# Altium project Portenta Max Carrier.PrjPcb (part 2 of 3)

## Sheet HDConn_FEMALE.SchDoc: HD Connectors female
size A3; Author: Arturo Guadalupi; CompanyName: Arduino srl; DocumentNumber: ABX00043; Revision: V3.10; SheetNumber: 2; SheetTotal: 14; RevAuthor: S. Navaretti
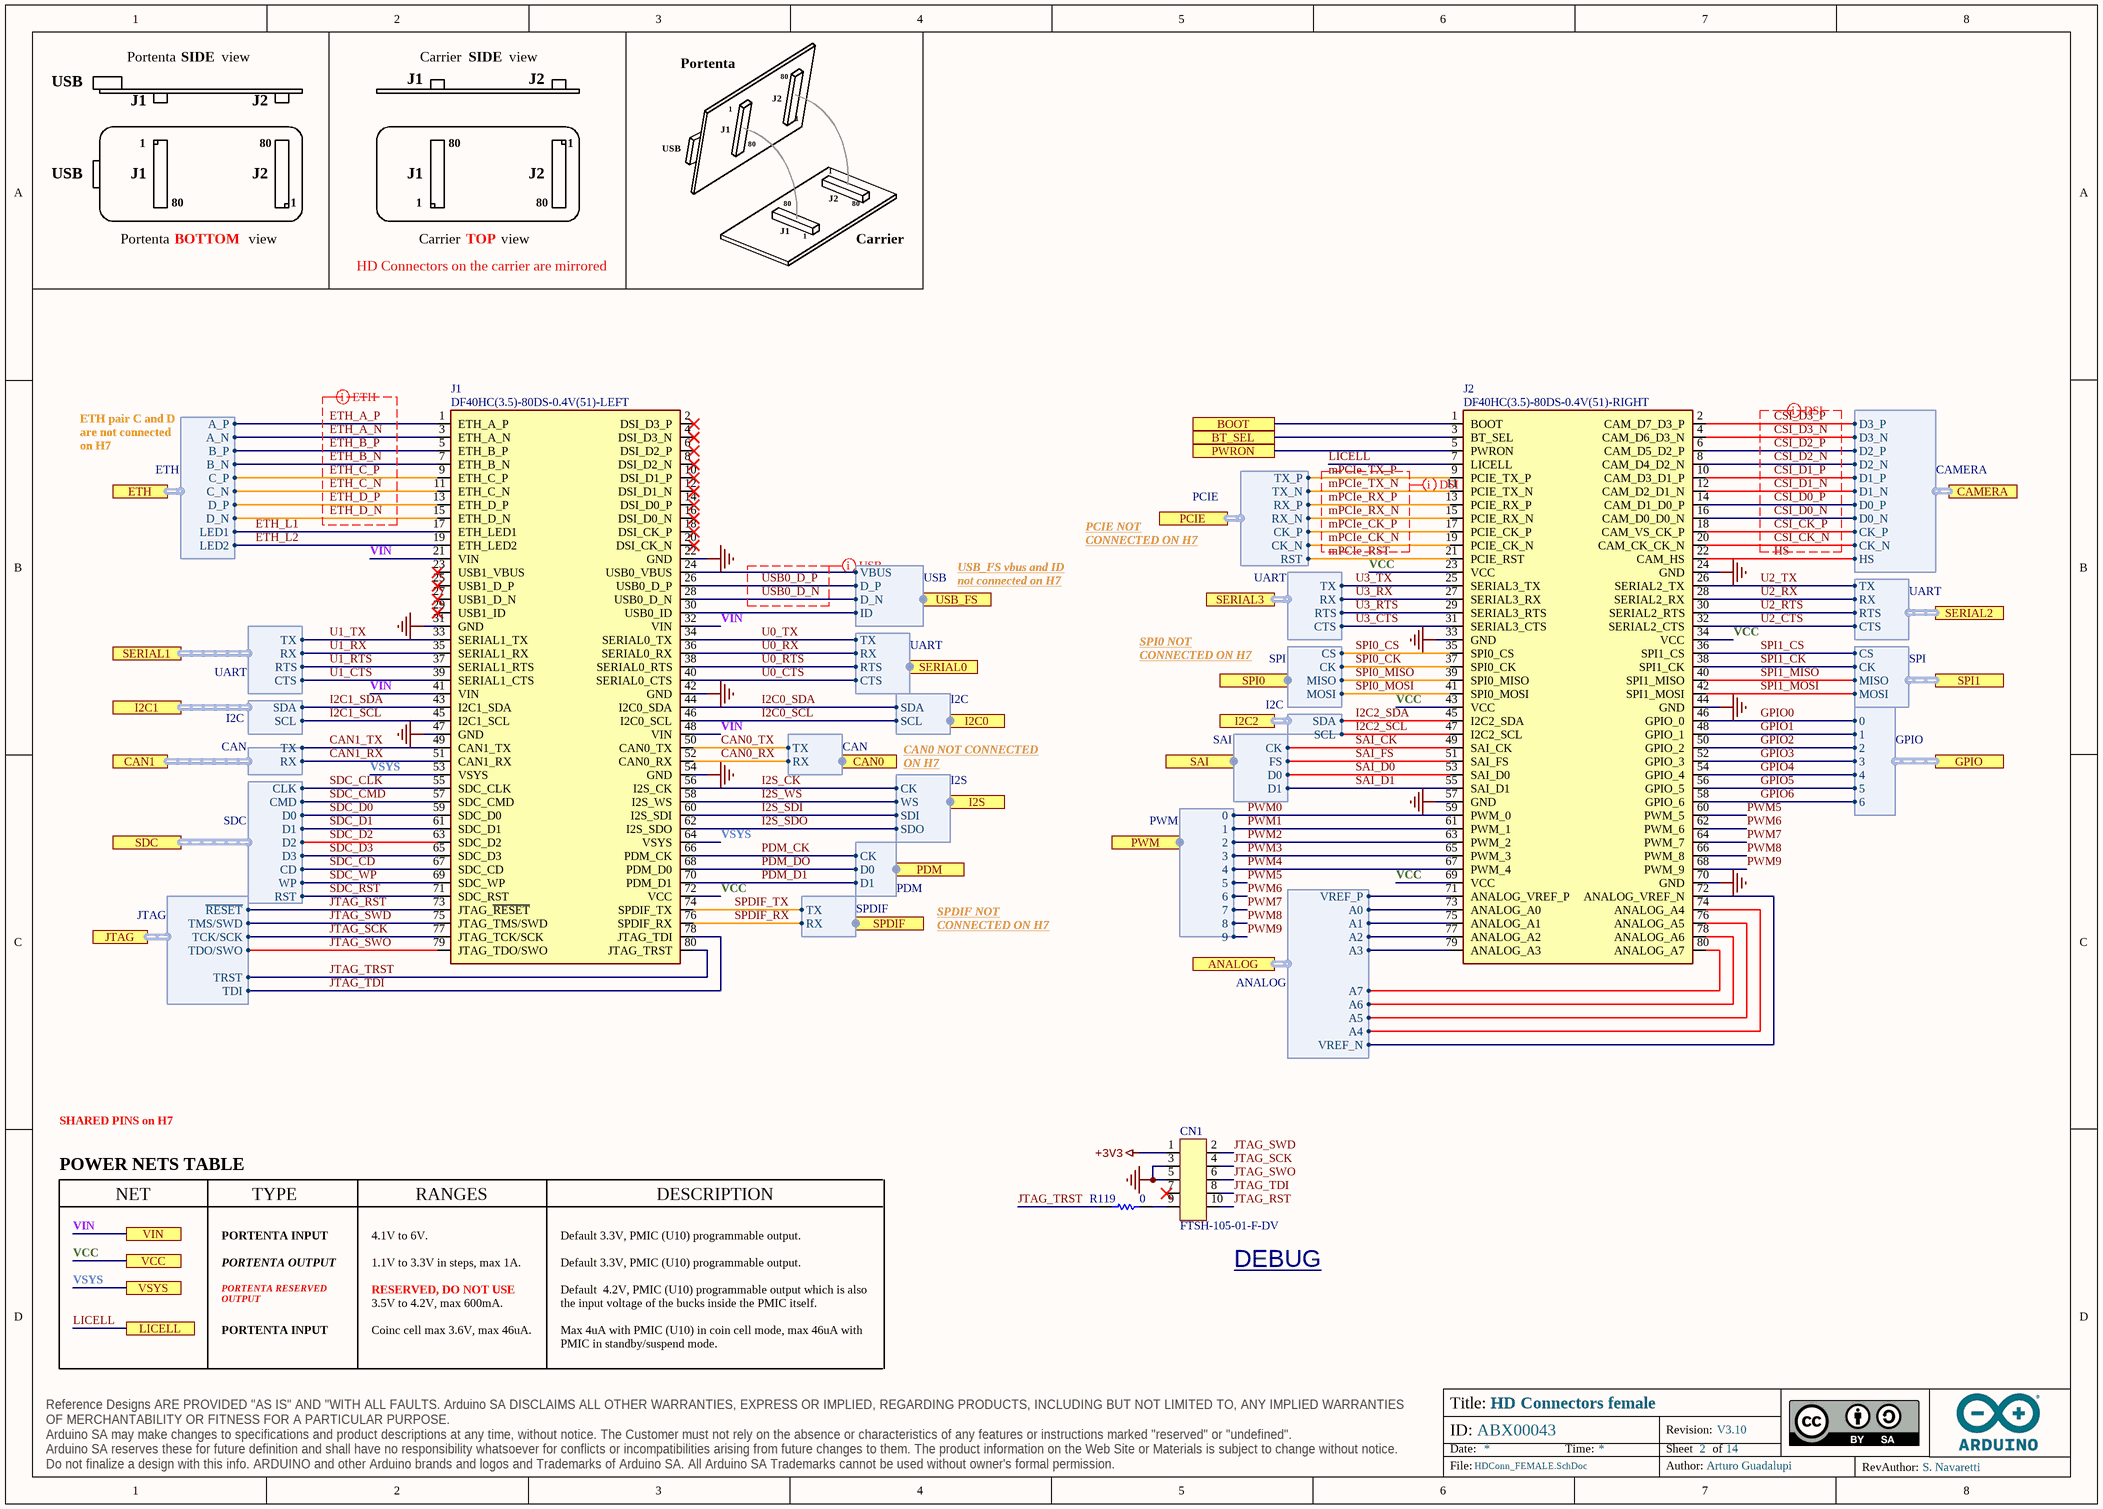
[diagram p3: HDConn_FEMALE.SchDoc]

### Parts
CN1  FTSH-105-01-F-DV  [FTSH-105-01-F-DV-Footprint-1]
J1  DF40HC(3.5)-80DS-0.4V(51)-LEFT  [DF40HC(3.5)-80DS-0.4V(51)-Footprint-1]
J2  DF40HC(3.5)-80DS-0.4V(51)-RIGHT  [DF40HC(3.5)-80DS-0.4V(51)-Footprint-1]
R119  value 0  [RES-0402]  (hidden comment: CRCW04020000Z0EDC)

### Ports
ANALOG (harness ANALOG), BOOT, BT_SEL, CAMERA (harness CAMERA), CAN0 (harness CAN), CAN1 (harness CAN), ETH (harness ETH), GPIO (harness GPIO), I2C0 (harness I2C), I2C1 (harness I2C), I2C2 (harness I2C), I2S (harness I2S), JTAG (harness JTAG), LICELL, PCIE (harness PCIE), PDM (harness PDM), PWM (harness PWM), PWRON, SAI (harness SAI), SDC (harness SDC), SERIAL0 (harness UART), SERIAL1 (harness UART), SERIAL2 (harness UART), SERIAL3 (harness UART), SPDIF (harness SPDIF), SPI0 (harness SPI), SPI1 (harness SPI), USB_FS (harness USB), VCC, VIN, VSYS

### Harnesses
ANALOG: VREF_P, A0, A1, A2, A3, A7, A6, A5, A4, VREF_N
PWM: 0, 1, 2, 3, 4, 5, 6, 7, 8, 9
GPIO: 0, 1, 2, 3, 4, 5, 6
ETH: A_P, A_N, B_P, B_N, C_P, C_N, D_P, D_N, LED1, LED2
UART: RX, TX, RTS, CTS
I2C: SCL, SDA
CAN: RX, TX
SDC: CLK, CMD, D0, D1, D2, D3, CD, WP, RST
JTAG: ~{RESET}, TCK/SCK, TDI, TDO/SWO, TMS/SWD, TRST
USB: VBUS, D_P, D_N, ID
I2C: SDA, SCL
I2S: CK, SDI, SDO, WS
PDM: CK, D0, D1
SAI: CK, FS, D0, D1
SPI: CS, CK, MISO, MOSI
PCIE: TX_P, TX_N, RX_P, RX_N, CK_P, CK_N, RST
SPDIF: RX, TX
CAMERA: D3_P, D3_N, D2_P, D2_N, D1_P, D1_N, D0_P, D0_N, CK_P, CK_N, HS

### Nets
+3V3: CN1.1 J1.72(VCC) J2.23(VCC) J2.34(VCC) J2.43(VCC) J2.69(VCC) ; port VCC  [also labelled VCC]
GND: CN1.3 CN1.5 J1.22(GND) J1.31(GND) J1.42(GND) J1.47(GND) J1.54(GND) J2.24(GND) J2.33(GND) J2.44(GND) J2.57(GND) J2.70(GND)
VSYS: J1.53(VSYS) J1.64(VSYS) ; port VSYS
A0: J2.73(ANALOG_A0) ; port ANALOG.A0
A1: J2.75(ANALOG_A1) ; port ANALOG.A1
A2: J2.77(ANALOG_A2) ; port ANALOG.A2
A3: J2.79(ANALOG_A3) ; port ANALOG.A3
A4: J2.74(ANALOG_A4) ; port ANALOG.A4
A5: J2.76(ANALOG_A5) ; port ANALOG.A5
A6: J2.78(ANALOG_A6) ; port ANALOG.A6
A7: J2.80(ANALOG_A7) ; port ANALOG.A7
ANALOG.VREF_N: J2.72(ANALOG_VREF_N) ; port ANALOG.VREF_N
ANALOG.VREF_P: J2.71(ANALOG_VREF_P) ; port ANALOG.VREF_P
BOOT: J2.1(BOOT) ; port BOOT
BT_SEL: J2.3(BT_SEL) ; port BT_SEL
CAN0_RX: J1.52(CAN0_RX) ; port CAN0.RX  [project net CAN0.RX]
CAN0_TX: J1.50(CAN0_TX) ; port CAN0.TX  [project net CAN0.TX]
CAN1_RX: J1.51(CAN1_RX) ; port CAN1.RX  [project net CAN1.RX]
CAN1_TX: J1.49(CAN1_TX) ; port CAN1.TX  [project net CAN1.TX]
CSI_CK_N: J2.20(CAM_CK_CK_N) ; port CAMERA.CK_N  [project net CAMERA.CK_N]
CSI_CK_P: J2.18(CAM_VS_CK_P) ; port CAMERA.CK_P  [project net CAMERA.CK_P]
CSI_D0_N: J2.16(CAM_D0_D0_N) ; port CAMERA.D0_N  [project net CAMERA.D0_N]
CSI_D0_P: J2.14(CAM_D1_D0_P) ; port CAMERA.D0_P  [project net CAMERA.D0_P]
CSI_D1_N: J2.12(CAM_D2_D1_N) ; port CAMERA.D1_N  [project net CAMERA.D1_N]
CSI_D1_P: J2.10(CAM_D3_D1_P) ; port CAMERA.D1_P  [project net CAMERA.D1_P]
CSI_D2_N: J2.8(CAM_D4_D2_N) ; port CAMERA.D2_N  [project net CAMERA.D2_N]
CSI_D2_P: J2.6(CAM_D5_D2_P) ; port CAMERA.D2_P  [project net CAMERA.D2_P]
CSI_D3_N: J2.4(CAM_D6_D3_N) ; port CAMERA.D3_N  [project net CAMERA.D3_N]
CSI_D3_P: J2.2(CAM_D7_D3_P) ; port CAMERA.D3_P  [project net CAMERA.D3_P]
ETH_A_N: J1.3(ETH_A_N) ; port ETH.A_N  [project net ETH.A_N]
ETH_A_P: J1.1(ETH_A_P) ; port ETH.A_P  [project net ETH.A_P]
ETH_B_N: J1.7(ETH_B_N) ; port ETH.B_N  [project net ETH.B_N]
ETH_B_P: J1.5(ETH_B_P) ; port ETH.B_P  [project net ETH.B_P]
ETH_C_N: J1.11(ETH_C_N) ; port ETH.C_N  [project net ETH.C_N]
ETH_C_P: J1.9(ETH_C_P) ; port ETH.C_P  [project net ETH.C_P]
ETH_D_N: J1.15(ETH_D_N) ; port ETH.D_N  [project net ETH.D_N]
ETH_D_P: J1.13(ETH_D_P) ; port ETH.D_P  [project net ETH.D_P]
ETH_L1: J1.17(ETH_LED1) ; port ETH.LED1  [project net ETH.LED1]
ETH_L2: J1.19(ETH_LED2) ; port ETH.LED2  [project net ETH.LED2]
GPIO0: J2.46(GPIO_0) ; port GPIO.0  [project net AUDIO_MCLK_EN]
GPIO1: J2.48(GPIO_1) ; port GPIO.1  [project net AUDIO_RST]
GPIO2: J2.50(GPIO_2) ; port GPIO.2  [project net CELL_RST]
GPIO3: J2.52(GPIO_3) ; port GPIO.3  [project net GPIO.3]
GPIO4: J2.54(GPIO_4) ; port GPIO.4  [project net CELL_PON]
GPIO5: J2.56(GPIO_5) ; port GPIO.5  [project net FD_TX_TERM]
GPIO6: J2.58(GPIO_6) ; port GPIO.6  [project net GPIO.6]
HS: J2.22(CAM_HS) ; port CAMERA.HS  [project net CAMERA.HS]
I2C0_SCL: J1.46(I2C0_SCL) ; port I2C0.SCL  [project net I2C0.SCL]
I2C0_SDA: J1.44(I2C0_SDA) ; port I2C0.SDA  [project net I2C0.SDA]
I2C1_SCL: J1.45(I2C1_SCL) ; port I2C1.SCL  [project net I2C1.SCL]
I2C1_SDA: J1.43(I2C1_SDA) ; port I2C1.SDA  [project net I2C1.SDA]
I2C2_SCL: J2.47(I2C2_SCL) ; port I2C2.SCL  [project net I2C2.SCL]
I2C2_SDA: J2.45(I2C2_SDA) ; port I2C2.SDA  [project net I2C2.SDA]
I2S_CK: J1.56(I2S_CK) ; port I2S.CK  [project net I2S.CK]
I2S_SDI: J1.60(I2S_SDI) ; port I2S.SDI  [project net I2S.SDI]
I2S_SDO: J1.62(I2S_SDO) ; port I2S.SDO  [project net I2S.SDO]
I2S_WS: J1.58(I2S_WS) ; port I2S.WS  [project net I2S.WS]
JTAG_RST: CN1.10 J1.73(JTAG_~{RESET}) ; port JTAG.~{RESET}  [project net JTAG.~{RESET}]
JTAG_SCK: CN1.4 J1.77(JTAG_TCK/SCK) ; port JTAG.TCK/SCK  [project net JTAG.TCK/SCK]
JTAG_SWD: CN1.2 J1.75(JTAG_TMS/SWD) ; port JTAG.TMS/SWD  [project net JTAG.TMS/SWD]
JTAG_SWO: CN1.6 J1.79(JTAG_TDO/SWO) ; port JTAG.TDO/SWO  [project net JTAG.TDO/SWO]
JTAG_TDI: CN1.8 J1.78(JTAG_TDI) ; port JTAG.TDI  [project net JTAG.TDI]
JTAG_TRST: J1.80(JTAG_TRST) R119.1 ; port JTAG.TRST  [project net JTAG.TRST]
LICELL: J2.7(LICELL) ; port LICELL
mPCIe_CK_N: J2.19(PCIE_CK_N) ; port PCIE.CK_N  [project net PCIe.CK_N]
mPCIe_CK_P: J2.17(PCIE_CK_P) ; port PCIE.CK_P  [project net PCIe.CK_P]
mPCIe_RST: J2.21(PCIE_RST) ; port PCIE.RST  [project net PCIe.RST]
mPCIe_RX_N: J2.15(PCIE_RX_N) ; port PCIE.RX_N  [project net PCIe.RX_N]
mPCIe_RX_P: J2.13(PCIE_RX_P) ; port PCIE.RX_P  [project net PCIe.RX_P]
mPCIe_TX_N: J2.11(PCIE_TX_N) ; port PCIE.TX_N  [project net PCIe.TX_N]
mPCIe_TX_P: J2.9(PCIE_TX_P) ; port PCIE.TX_P  [project net PCIe.TX_P]
PDM_CK: J1.66(PDM_CK) ; port PDM.CK  [project net PDM.CK]
PDM_D1: J1.70(PDM_D1) ; port PDM.D1  [project net PDM.D1]
PDM_DO: J1.68(PDM_D0) ; port PDM.D0  [project net PDM.D0]
PWM0: J2.59(PWM_0) ; port PWM.0  [project net H/Fn]
PWM1: J2.61(PWM_1) ; port PWM.1  [project net 485/232n]
PWM2: J2.63(PWM_2) ; port PWM.2  [project net EN_485]
PWM3: J2.65(PWM_3) ; port PWM.3  [project net ~{EN_CAN}]
PWM4: J2.67(PWM_4) ; port PWM.4  [project net LORA_BOOT0]
PWM5: J2.60(PWM_5) ; port PWM.5  [project net LORA_IRQ]
PWM6: J2.62(PWM_6) ; port PWM.6  [project net PWM.6]
PWM7: J2.64(PWM_7) ; port PWM.7  [project net PWM.7]
PWM8: J2.66(PWM_8) ; port PWM.8  [project net PWM.8]
PWM9: J2.68(PWM_9) ; port PWM.9  [project net PWM.9]
SAI_CK: J2.49(SAI_CK) ; port SAI.CK  [project net SAI.CK]
SAI_D0: J2.53(SAI_D0) ; port SAI.D0  [project net SAI.D0]
SAI_D1: J2.55(SAI_D1) ; port SAI.D1  [project net SAI.D1]
SAI_FS: J2.51(SAI_FS) ; port SAI.FS  [project net SAI.FS]
SDC_CD: J1.67(SDC_CD) ; port SDC.CD  [project net SDC.CD]
SDC_CLK: J1.55(SDC_CLK) ; port SDC.CLK  [project net SDC.CLK]
SDC_CMD: J1.57(SDC_CMD) ; port SDC.CMD  [project net SDC.CMD]
SDC_D0: J1.59(SDC_D0) ; port SDC.D0  [project net SDC.D0]
SDC_D1: J1.61(SDC_D1) ; port SDC.D1  [project net SDC.D1]
SDC_D2: J1.63(SDC_D2) ; port SDC.D2  [project net SDC.D2]
SDC_D3: J1.65(SDC_D3) ; port SDC.D3  [project net SDC.D3]
SDC_RST: J1.71(SDC_RST) ; port SDC.RST  [project net SDC.RST]
SDC_WP: J1.69(SDC_WP) ; port SDC.WP  [project net SDC.WP]
SPDIF_RX: J1.76(SPDIF_RX) ; port SPDIF.RX  [project net SPDIF.RX]
SPDIF_TX: J1.74(SPDIF_TX) ; port SPDIF.TX  [project net SPDIF.TX]
SPI0_CK: J2.37(SPI0_CK) ; port SPI0.CK
SPI0_CS: J2.35(SPI0_CS) ; port SPI0.CS
SPI0_MISO: J2.39(SPI0_MISO) ; port SPI0.MISO
SPI0_MOSI: J2.41(SPI0_MOSI) ; port SPI0.MOSI
SPI1_CK: J2.38(SPI1_CK) ; port SPI1.CK  [project net SPI1.CK]
SPI1_CS: J2.36(SPI1_CS) ; port SPI1.CS  [project net SPI1.CS]
SPI1_MISO: J2.40(SPI1_MISO) ; port SPI1.MISO  [project net SPI1.MISO]
SPI1_MOSI: J2.42(SPI1_MOSI) ; port SPI1.MOSI  [project net SPI1.MOSI]
U0_CTS: J1.40(SERIAL0_CTS) ; port SERIAL0.CTS  [project net SERIAL0.CTS]
U0_RTS: J1.38(SERIAL0_RTS) ; port SERIAL0.RTS  [project net SERIAL0.RTS]
U0_RX: J1.36(SERIAL0_RX) ; port SERIAL0.RX  [project net SERIAL0.RX]
U0_TX: J1.34(SERIAL0_TX) ; port SERIAL0.TX  [project net SERIAL0.TX]
U1_CTS: J1.39(SERIAL1_CTS) ; port SERIAL1.CTS  [project net SERIAL1.CTS]
U1_RTS: J1.37(SERIAL1_RTS) ; port SERIAL1.RTS  [project net SERIAL1.RTS]
U1_RX: J1.35(SERIAL1_RX) ; port SERIAL1.RX  [project net SERIAL1.RX]
U1_TX: J1.33(SERIAL1_TX) ; port SERIAL1.TX  [project net SERIAL1.TX]
U2_CTS: J2.32(SERIAL2_CTS) ; port SERIAL2.CTS  [project net SERIAL2.CTS]
U2_RTS: J2.30(SERIAL2_RTS) ; port SERIAL2.RTS  [project net SERIAL2.RTS]
U2_RX: J2.28(SERIAL2_RX) ; port SERIAL2.RX  [project net SERIAL2.RX]
U2_TX: J2.26(SERIAL2_TX) ; port SERIAL2.TX  [project net SERIAL2.TX]
U3_CTS: J2.31(SERIAL3_CTS) ; port SERIAL3.CTS  [project net SERIAL3.CTS]
U3_RTS: J2.29(SERIAL3_RTS) ; port SERIAL3.RTS  [project net SERIAL3.RTS]
U3_RX: J2.27(SERIAL3_RX) ; port SERIAL3.RX  [project net SERIAL3.RX]
U3_TX: J2.25(SERIAL3_TX) ; port SERIAL3.TX  [project net SERIAL3.TX]
USB0_D_N: J1.28(USB0_D_N) ; port USB_FS.D_N  [project net USB_FS.D_N]
USB0_D_P: J1.26(USB0_D_P) ; port USB_FS.D_P  [project net USB_FS.D_P]
USB_FS.ID: J1.30(USB0_ID) ; port USB_FS.ID
USB_FS.VBUS: J1.24(USB0_VBUS) ; port USB_FS.VBUS
VIN: J1.21(VIN) J1.32(VIN) J1.41(VIN) J1.48(VIN) ; port VIN
NetCN1_9: CN1.9 R119.2
NetJ2_5: J2.5(PWRON) ; port PWRON

Not connected (* = marked no-connect by the designer): CN1 7*; J1 2(DSI_D3_P)* 4(DSI_D3_N)* 6(DSI_D2_P)* 8(DSI_D2_N)* 10(DSI_D1_P)* 12(DSI_D1_N)* 14(DSI_D0_P)* 16(DSI_D0_N)* 18(DSI_CK_P)* 20(DSI_CK_N)* 23(USB1_VBUS)* 25(USB1_D_P)* 27(USB1_D_N)* 29(USB1_ID)*

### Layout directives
differential pair; differential pair class ETH: ETH_A_N, ETH_A_P, ETH_B_N, ETH_B_P, ETH_C_N, ETH_C_P, ETH_D_N, ETH_D_P
differential pair; differential pair class USB: USB0_D_N, USB0_D_P
differential pair; differential pair class DSI: mPCIe_CK_N, mPCIe_CK_P, mPCIe_RX_N, mPCIe_RX_P, mPCIe_TX_N, mPCIe_TX_P
differential pair; differential pair class CAMERA: CSI_CK_N, CSI_CK_P, CSI_D0_N, CSI_D0_P, CSI_D1_N, CSI_D1_P, CSI_D2_N, CSI_D2_P, CSI_D3_N, CSI_D3_P

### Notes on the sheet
- USB
- Portenta
- J1
- SIDE
- view
- J2
- Carrier
- 1
- 80
- BOTTOM
- TOP
- HD Connectors on the carrier are mirrored
- ETH pair C and D are not connected on H7
- USB_FS vbus and ID
  not connected on H7
- PCIE NOT CONNECTED ON H7
- SPI0 NOT CONNECTED ON H7
- CAN0 NOT CONNECTED ON H7
- SPDIF NOT CONNECTED ON H7
- SHARED PINS on H7
- POWER NETS TABLE
- NET
- TYPE
- PORTENTA INPUT
- PORTENTA OUTPUT
- RANGES
- 4.1V to 6V.
- 1.1V to 3.3V in steps, max 1A.
- DESCRIPTION
- Default 3.3V, PMIC (U10) programmable output.
- PORTENTA RESERVED OUTPUT
- RESERVED, DO NOT USE
- 3.5V to 4.2V, max 600mA.
- Default  4.2V, PMIC (U10) programmable output which is also the input voltage of the bucks inside the PMIC itself.
- DEBUG
- Coinc cell max 3.6V, max 46uA.
- Max 4uA with PMIC (U10) in coin cell mode, max 46uA with PMIC in standby/suspend mode.

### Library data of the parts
CN1 = J0089-A.6: CONN HEADER SMD 10POS 2x5 1.27MM JTAG; Manufacturer: Samtec; Number of Contacts: 10; Row Spacing: 0.05inch; Current Rating: 1.75A; Code Arduino: J0089; Gender: Male; Connector Type: Male Pin
J1 = J0016-A.9: CONN RCPT FEMALE D80POS 0.4MM SMD GOLD; Manufacturer: Hirose; Number of Contacts: 80; Current Rating: 300mA; Voltage Rating: 30V; Stack Height: 3.5mm; Code Arduino: J0016; Gender: Receptacle; Pitch: 0.016inch
J2 = J0153-A.2: CONN RCPT FEMALE D80POS 0.4MM SMD GOLD; Manufacturer: Hirose; Number of Contacts: 80; Current Rating: 300mA; Voltage Rating: 30V; Stack Height: 3.5mm; Code Arduino: J0016; Gender: Receptacle; Pitch: 0.016inch
R119 = R0000-A.5: RES CHIP 0402 0R 1/16W; Manufacturer: Vishay; Code Arduino: 0039; Power: 63mW; Tolerance: J

## Sheet AUDIO.SchDoc: AUDIO
size A4; Author: Arturo Guadalupi; CompanyName: Arduino srl; DocumentNumber: ABX00043; Revision: V3.10; SheetNumber: 4; SheetTotal: 14; RevAuthor: S. Navaretti
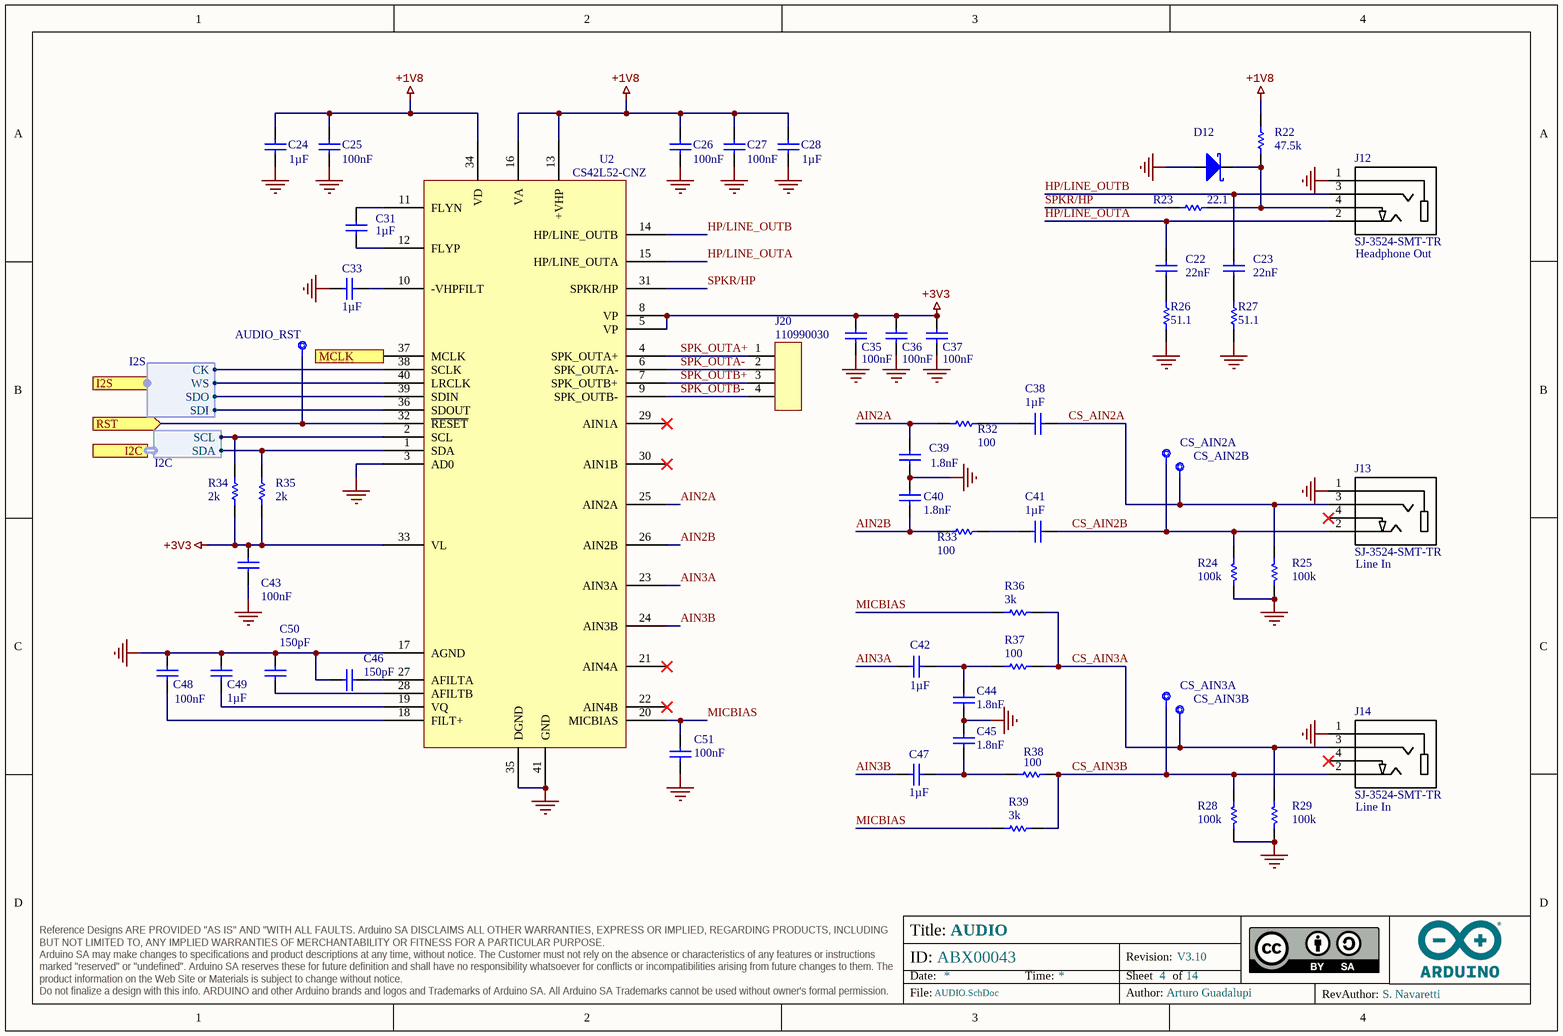
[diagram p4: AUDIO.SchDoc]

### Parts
AUDIO_RST  CMP-018-0005-A.3  [TP-1.00MM]  (value not drawn)  (no BOM)
C22  value 22nF  [CAP-0402]  (hidden comment: CL05B223KP5NNNC)
C23  value 22nF  [CAP-0402]  (hidden comment: CL05B223KP5NNNC)
C24  value 1µF  [CAP-0402]  (hidden comment: C0402C105K8PACTU)
C25  value 100nF  [CAP-0402]  (hidden comment: C0402C104K4RACTU)
C26  value 100nF  [CAP-0402]  (hidden comment: C0402C104K4RACTU)
C27  value 100nF  [CAP-0402]  (hidden comment: C0402C104K4RACTU)
C28  value 1µF  [CAP-0402]  (hidden comment: C0402C105K8PACTU)
C31  value 1µF  [CAP-0402]  (hidden comment: C0402C105K8PACTU)
C33  value 1µF  [CAP-0402]  (hidden comment: C0402C105K8PACTU)
C35  value 100nF  [CAP-0402]  (hidden comment: C0402C104K4RACTU)
C36  value 100nF  [CAP-0402]  (hidden comment: C0402C104K4RACTU)
C37  value 100nF  [CAP-0402]  (hidden comment: C0402C104K4RACTU)
C38  value 1µF  [CAP-0402]  (hidden comment: C0402C105K8PACTU)
C39  value 1.8nF  [CAP-0402]  (hidden comment: C0402C182J3GAC7867)
C40  value 1.8nF  [CAP-0402]  (hidden comment: C0402C182J3GAC7867)
C41  value 1µF  [CAP-0402]  (hidden comment: C0402C105K8PACTU)
C42  value 1µF  [CAP-0402]  (hidden comment: C0402C105K8PACTU)
C43  value 100nF  [CAP-0402]  (hidden comment: C0402C104K4RACTU)
C44  value 1.8nF  [CAP-0402]  (hidden comment: C0402C182J3GAC7867)
C45  value 1.8nF  [CAP-0402]  (hidden comment: C0402C182J3GAC7867)
C46  value 150pF  [CAP-0402]  (hidden comment: GRM1555C1H151FA01D)
C47  value 1µF  [CAP-0402]  (hidden comment: C0402C105K8PACTU)
C48  value 100nF  [CAP-0402]  (hidden comment: C0402C104K4RACTU)
C49  value 1µF  [CAP-0402]  (hidden comment: C0402C105K8PACTU)
C50  value 150pF  [CAP-0402]  (hidden comment: GRM1555C1H151FA01D)
C51  value 100nF  [CAP-0402]  (hidden comment: C0402C104K4RACTU)
CS_AIN2A  CMP-018-0005-A.3  [TP-1.00MM]  (value not drawn)  (no BOM)
CS_AIN2B  CMP-018-0005-A.3  [TP-1.00MM]  (value not drawn)  (no BOM)
CS_AIN3A  CMP-018-0005-A.3  [TP-1.00MM]  (value not drawn)  (no BOM)
CS_AIN3B  CMP-018-0005-A.3  [TP-1.00MM]  (value not drawn)  (no BOM)
D12  PESD0402-140CT-ND  [0402]  (value not drawn)
J12  SJ-3524-SMT-TR  [SJ-3524-SMT-TR-Footprint-1]
J13  SJ-3524-SMT-TR  [SJ-3524-SMT-TR-Footprint-1]
J14  SJ-3524-SMT-TR  [SJ-3524-SMT-TR-Footprint-1]
J20  110990030  [HW4-2.0]
R22  value 47.5k  [RES-0402]  (hidden comment: CRCW040247K5FKED)
R23  value 22.1  [RES-0402]  (hidden comment: CRCW040222R1FKED)
R24  value 100k  [RES-0402]  (hidden comment: CRCW0402100KFKEDC)
R25  value 100k  [RES-0402]  (hidden comment: CRCW0402100KFKEDC)
R26  value 51.1  [RES-0402]  (hidden comment: CRCW040251R1FKED)
R27  value 51.1  [RES-0402]  (hidden comment: CRCW040251R1FKED)
R28  value 100k  [RES-0402]  (hidden comment: CRCW0402100KFKEDC)
R29  value 100k  [RES-0402]  (hidden comment: CRCW0402100KFKEDC)
R32  value 100  [RES-0402]  (hidden comment: CRCW0402100RJNED)
R33  value 100  [RES-0402]  (hidden comment: CRCW0402100RJNED)
R34  value 2k  [RES-0402]  (hidden comment: CRCW04022K00JNED)
R35  value 2k  [RES-0402]  (hidden comment: CRCW04022K00JNED)
R36  value 3k  [RES-0402]  (hidden comment: CRCW04023K00JNED)
R37  value 100  [RES-0402]  (hidden comment: CRCW0402100RJNED)
R38  value 100  [RES-0402]  (hidden comment: CRCW0402100RJNED)
R39  value 3k  [RES-0402]  (hidden comment: CRCW04023K00JNED)
U2  CS42L52-CNZ  [QFN127P600-8N]

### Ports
I2C (harness I2C), I2S (harness I2S), MCLK (in), RST (in)

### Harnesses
I2C: SCL, SDA
I2S: CK, SDI, SDO, WS

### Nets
+1V8: C24.2 C25.2 C26.2 C27.2 C28.2 R22.2 U2.13(+VHP) U2.16(VA) U2.34(VD)
+3V3: C35.2 C36.2 C37.2 C43.2 R34.1 R35.1 U2.5(VP) U2.8(VP) U2.33(VL)
GND: C24.1 C25.1 C26.1 C27.1 C28.1 C33.2 C35.1 C36.1 C37.1 C39.1 C40.2 C43.1 C44.1 C45.2 C46.2 C48.2 C49.2 C50.2 C51.1 D12.A J12.1 J13.1 J14.1 R24.1 R25.1 R26.1 R27.1 R28.1 R29.1 U2.3(AD0) U2.17(AGND) U2.35(DGND) U2.41(GND)
AIN2A: C39.2 R32.1 U2.25(AIN2A)  [project net AIN2A_4]
AIN2B: C40.1 R33.1 U2.26(AIN2B)  [project net AIN2B_4]
AIN3A: C42.1 U2.23(AIN3A)  [project net AIN3A_4]
AIN3B: C47.1 U2.24(AIN3B)  [project net AIN3B_4]
AUDIO_RST: AUDIO_RST.X U2.32(~{RESET}) ; port RST
CS_AIN2A: C38.2 CS_AIN2B.X J13.3 R25.2  [project net CS_AIN2A_4]
CS_AIN2B: C41.2 CS_AIN2A.X J13.2 R24.2  [project net CS_AIN2B_4]
CS_AIN3A: CS_AIN3B.X J14.3 R29.2 R36.2 R37.2  [project net CS_AIN3A_4]
CS_AIN3B: CS_AIN3A.X J14.2 R28.2 R38.2 R39.2  [project net CS_AIN3B_4]
HP/LINE_OUTA: C22.2 J12.2 U2.15(HP/LINE_OUTA)  [project net HP/LINE_OUTA_4]
HP/LINE_OUTB: C23.2 J12.3 U2.14(HP/LINE_OUTB)  [project net HP/LINE_OUTB_4]
I2C0.SCL: R34.2 U2.2(SCL) ; port I2C.SCL
I2C0.SDA: R35.2 U2.1(SDA) ; port I2C.SDA
I2S.CK: U2.38(SCLK) ; port I2S.CK
I2S.SDI: U2.36(SDOUT) ; port I2S.SDI
I2S.SDO: U2.39(SDIN) ; port I2S.SDO
I2S.WS: U2.40(LRCLK) ; port I2S.WS
MICBIAS: C51.2 R36.1 R39.1 U2.20(MICBIAS)  [project net MICBIAS_4]
SPK_OUTA+: J20.1 U2.4(SPK_OUTA+)  [project net SPK_OUTA+_4]
SPK_OUTA-: J20.2 U2.6(SPK_OUTA-)  [project net SPK_OUTA-_4]
SPK_OUTB+: J20.3 U2.7(SPK_OUTB+)  [project net SPK_OUTB+_4]
SPK_OUTB-: J20.4 U2.9(SPK_OUTB-)  [project net SPK_OUTB-_4]
SPKR/HP: R23.1 U2.31(SPKR/HP)  [project net SPKR/HP_4]
NetAUDIO_MCLK_X: U2.37(MCLK) ; port MCLK
NetC22_1: C22.1 R26.2
NetC23_1: C23.1 R27.2
NetC31_1: C31.1 U2.12(FLYP)
NetC31_2: C31.2 U2.11(FLYN)
NetC33_1: C33.1 U2.10(-VHPFILT)
NetC38_1: C38.1 R32.2
NetC41_1: C41.1 R33.2
NetC42_2: C42.2 C44.2 R37.1
NetC45_1: C45.1 C47.2 R38.1
NetC46_1: C46.1 U2.27(AFILTA)
NetC48_1: C48.1 U2.18(FILT+)
NetC49_1: C49.1 U2.19(VQ)
NetC50_1: C50.1 U2.28(AFILTB)
NetD12_C: D12.C J12.4 R22.1 R23.2

Not connected (* = marked no-connect by the designer): J13 4*; J14 4*; U2 21(AIN4A)* 22(AIN4B)* 29(AIN1A)* 30(AIN1B)*

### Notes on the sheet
- (near J12) Headphone Out
- (near J13) Line In
- (near J14) Line In

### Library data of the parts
AUDIO_RST CS_AIN2A CS_AIN2B CS_AIN3A CS_AIN3B = UT0013-A.2: Test point 1.00mm
C22 C23 = C0033-A.9: CAP CHIP 0402 22NF 10V X7R 10%; Manufacturer: Samsung Electro-Mechanics; Code Arduino: C0033
C24 C28 C31 C33 C38 C41 C42 C47 C49 = C0017-A.9: CAP CHIP 0402 1uF 10V X5R 10%; Manufacturer: KEMET; Code Arduino: 0133
C25-C27 C35-C37 C43 C48 C51 = C0012-A.9: CAP CHIP 0402 100nF 16V X7R 10%; Manufacturer: KEMET; Code Arduino: 0132
C39 C40 C44 C45 = C0073-A.7: CAP CHIP 0402 1.8NF 25V C0G 5%; Manufacturer: KEMET; Code Arduino: C0073
C46 C50 = C0074-A.7: CAP CHIP 0402 150PF 50V C0G 1%; Manufacturer: Murata; Code Arduino: C0074
D12 = D0027-A.3: DIODE TVS SMD 0402 14V 40V; Manufacturer: Littelfuse Inc; Device Type: ESD protection; Code Arduino: 2280
J12-J14 = J0020-A.3: CONN JACK STEREO 3.5MM SMD R/A; Manufacturer: CUI; Gender: Female; Current Rating: 1A; Code Arduino: J0020; Number of Ports: 1; Shielding: Unshielded; Number of Conductors: 3
J20 = J0003-A.4: CONN GROVE EQUIV THD 90 4POS; Manufacturer: Seeed; Code Arduino: 2240
R22 = R0076-A.6: RES CHIP 0402 47K5 1% 1/16W; Manufacturer: Vishay; Power: 63mW; Code Arduino: R0076
R23 = R0144-A.3: RES CHIP 0402 22R1 1% 1/16W; Manufacturer: Vishay; Power: 63mW; Code Arduino: R0144
R24 R25 R28 R29 = R0001-A.5: RES CHIP 0402 100K 1% 1/16W; Manufacturer: Vishay; Power: 63mW; Code Arduino: 0134
R26 R27 = R0143-A.3: RES CHIP 0402 51R1 1% 1/16W; Manufacturer: Yageo; Power: 63mW; Code Arduino: R0143
R32 R33 R37 R38 = R0042-A.6: RES CHIP 0402 100R 5% 1/16W; Manufacturer: Vishay; Power: 63mW; Code Arduino: 0131
R34 R35 = R0166-A.4: RES CHIP 0402 2K 5% 1/16W; Manufacturer: Vishay; Tolerance: 1%; Power: 63mW; Code Arduino: R0166
R36 R39 = R0139-A.3: RES CHIP 0402 3k 5% 1/16W; Manufacturer: Vishay; Tolerance: 1%; Power: 63mW; Code Arduino: R0139
U2 = U0053-A.4: IC CODEC STER HDPN & SPKR 40QFN; Manufacturer: Cirrus Logic; Number of A/D Converters: 1; Operating Supply Voltage: 2.5V; Code Arduino: U0053; Interface: Serial,I2C,SPI; Resolution: 24b; Sampling Rate: 96KS/s

## Sheet MINI_PCIE.SchDoc: MINI PCIE
size A3; Author: Arturo Guadalupi; CompanyName: Arduino srl; DocumentNumber: ABX00043; Revision: V3.10; SheetNumber: 7; SheetTotal: 14; RevAuthor: S. Navaretti
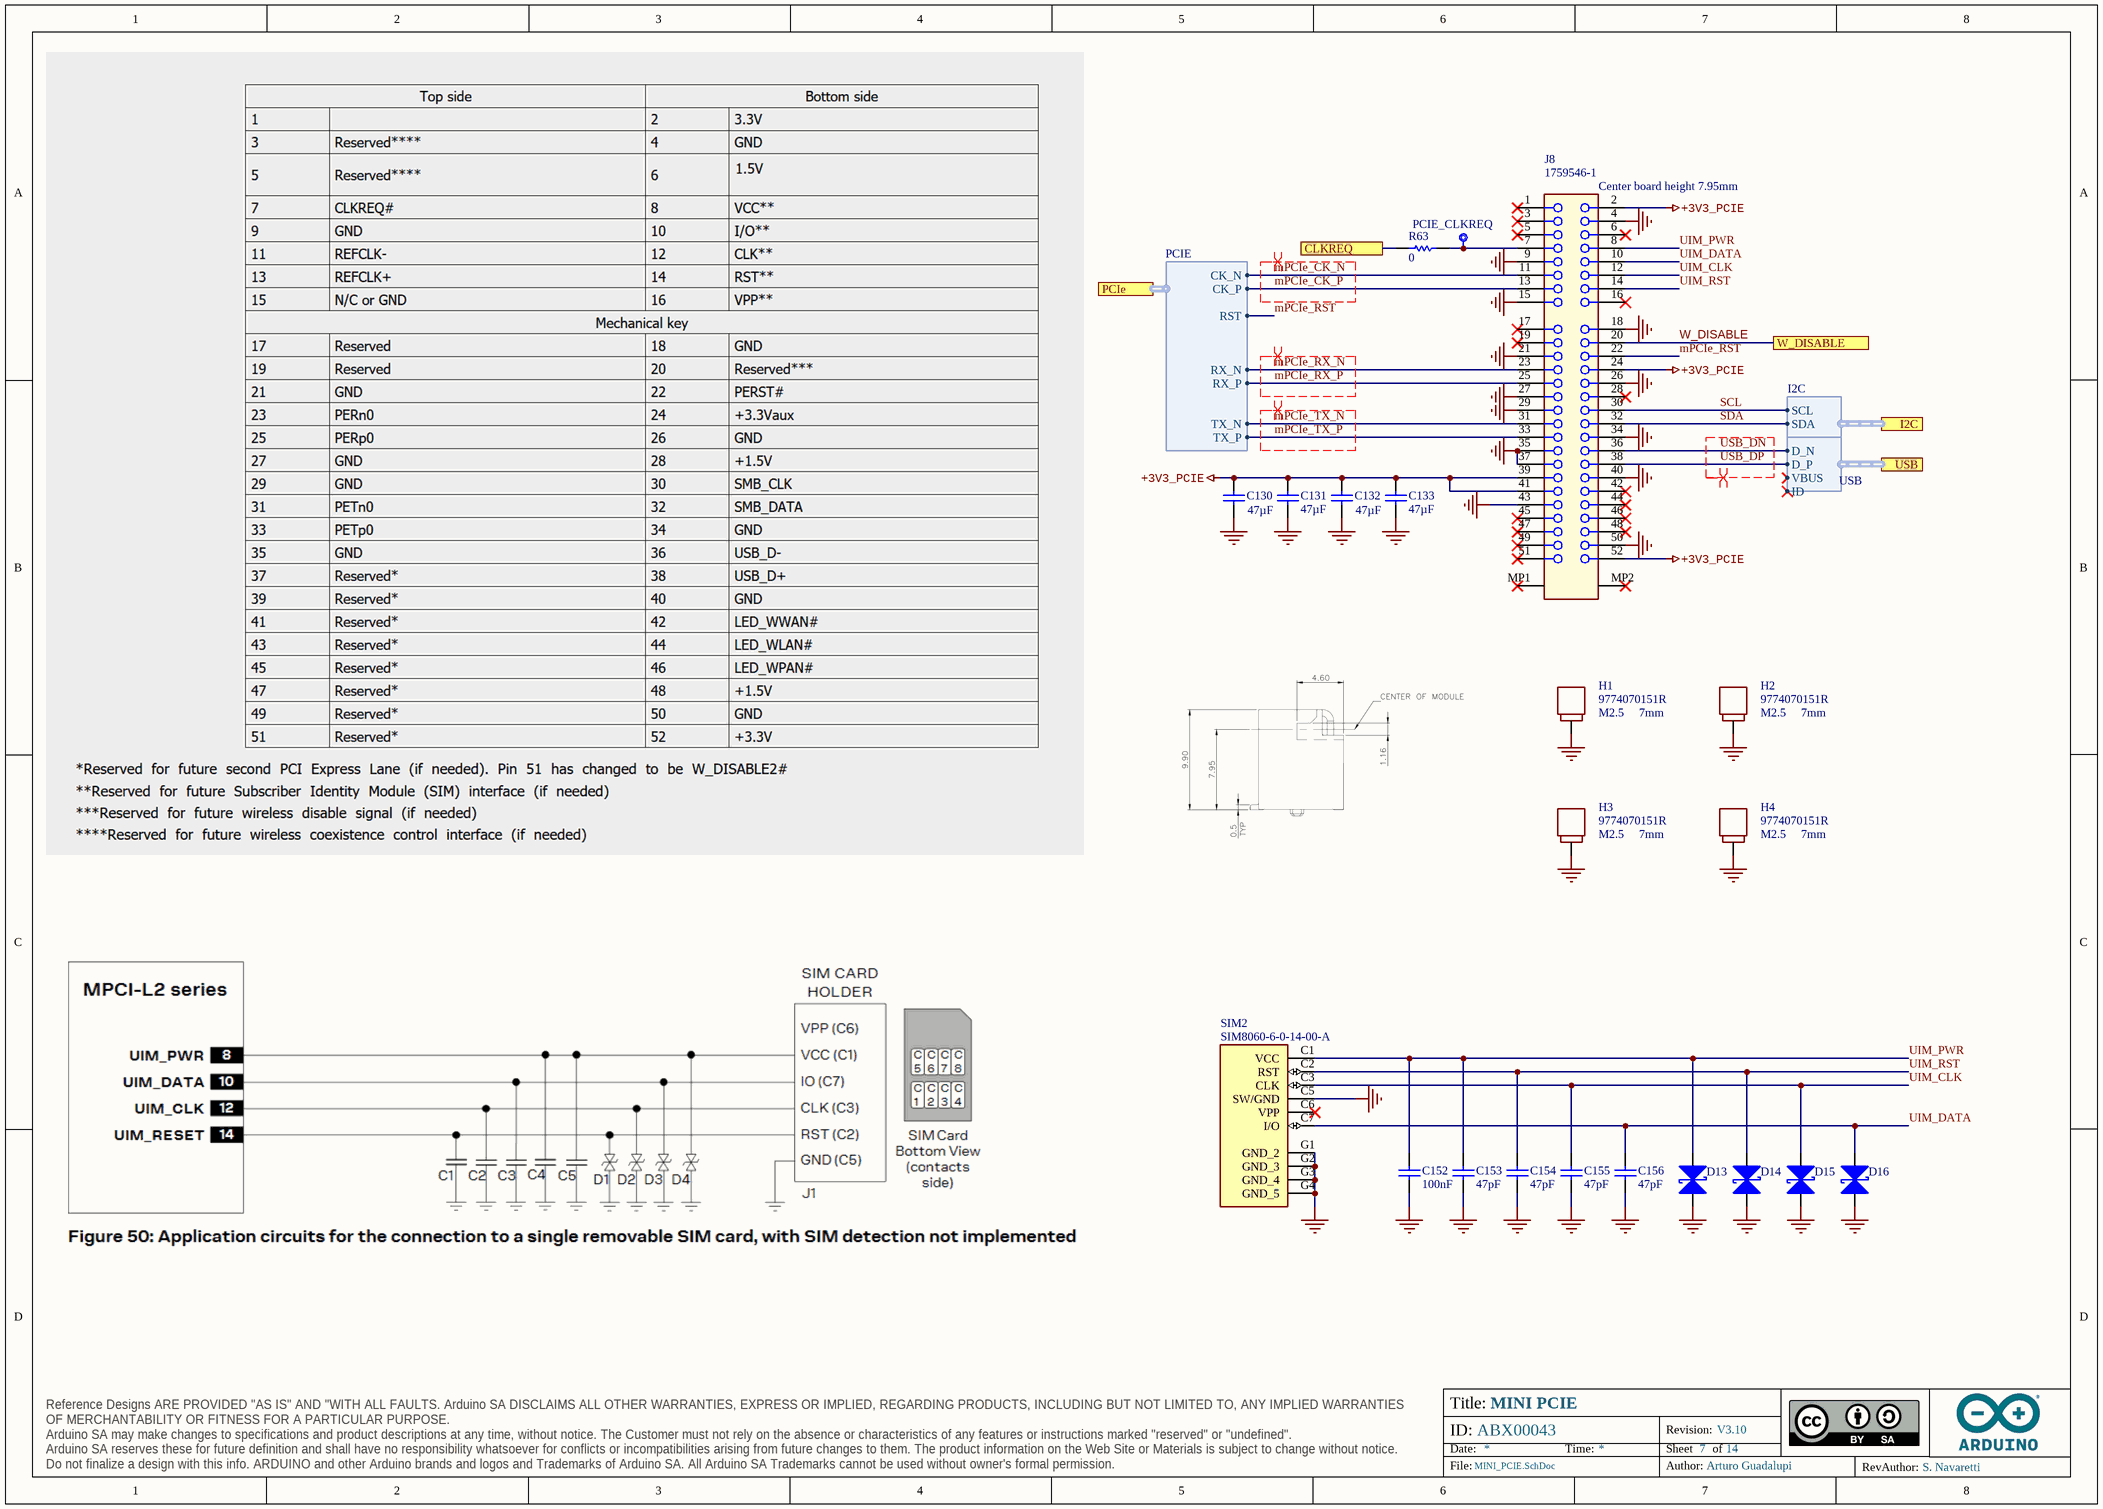
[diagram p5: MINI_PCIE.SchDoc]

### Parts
C130  value 47µF  [CAP-0603]  (hidden comment: ZRB18AR60J476ME01L)
C131  value 47µF  [CAP-0603]  (hidden comment: ZRB18AR60J476ME01L)
C132  value 47µF  [CAP-0603]  (hidden comment: ZRB18AR60J476ME01L)
C133  value 47µF  [CAP-0603]  (hidden comment: ZRB18AR60J476ME01L)
C152  value 100nF  [CAP-0402]  (hidden comment: C0402C104K4RACTU)
C153  value 47pF  [CAP-0402]  (hidden comment: CC0402JRNPO8BN470)
C154  value 47pF  [CAP-0402]  (hidden comment: CC0402JRNPO8BN470)
C155  value 47pF  [CAP-0402]  (hidden comment: CC0402JRNPO8BN470)
C156  value 47pF  [CAP-0402]  (hidden comment: CC0402JRNPO8BN470)
D13  PESD0402-140  [0402]  (value not drawn)
D14  PESD0402-140  [0402]  (value not drawn)
D15  PESD0402-140  [0402]  (value not drawn)
D16  PESD0402-140  [0402]  (value not drawn)
H1  9774070151R  [9774070151R]
H2  9774070151R  [9774070151R]
H3  9774070151R  [9774070151R]
H4  9774070151R  [9774070151R]
J8  1759546-1  [1759546-1]
PCIE_CLKREQ  CMP-018-0005-A.3  [TP-1.00MM]  (value not drawn)  (no BOM)
R63  value 0  [RES-0402]  (hidden comment: CRCW04020000Z0EDC)
SIM2  SIM8060-6-0-14-00-A  [SIM8060-6-0-14-00-A-Footprint-1]

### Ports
CLKREQ, I2C (harness I2C), PCIe (harness PCIE), USB (harness USB), W_DISABLE

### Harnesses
I2C: SCL, SDA
USB: D_N, D_P, VBUS, ID
PCIE: CK_N, CK_P, RX_N, RX_P, TX_N, TX_P, RST

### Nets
+3V3_PCIE: C130.2 C131.2 C132.2 C133.2 J8.2 J8.24 J8.39 J8.41 J8.52
GND: C130.1 C131.1 C132.1 C133.1 C152.1 C153.1 C154.1 C155.1 C156.1 D13.A D14.A D15.A D16.A H1.1 H2.1 H3.1 H4.1 J8.4 J8.9 J8.15 J8.18 J8.21 J8.26 J8.27 J8.29 J8.34 J8.35 J8.37 J8.40 J8.43 J8.50 SIM2.C5(SW/GND) SIM2.G1(GND_2) SIM2.G2(GND_3) SIM2.G3(GND_4) SIM2.G4(GND_5)
mPCIe_CK_N: J8.11 ; port PCIe.CK_N  [project net PCIe.CK_N]
mPCIe_CK_P: J8.13 ; port PCIe.CK_P  [project net PCIe.CK_P]
mPCIe_RST: J8.22 ; port PCIe.RST  [project net PCIe.RST]
mPCIe_RX_N: J8.23 ; port PCIe.RX_N  [project net PCIe.RX_N]
mPCIe_RX_P: J8.25 ; port PCIe.RX_P  [project net PCIe.RX_P]
mPCIe_TX_N: J8.31 ; port PCIe.TX_N  [project net PCIe.TX_N]
mPCIe_TX_P: J8.33 ; port PCIe.TX_P  [project net PCIe.TX_P]
PWM.9: R63.1 ; port CLKREQ
SCL: J8.30 ; port I2C.SCL  [project net I2C0.SCL]
SDA: J8.32 ; port I2C.SDA  [project net I2C0.SDA]
UIM_CLK: C155.2 D15.C J8.12 SIM2.C3(CLK)  [project net UIM_CLK_7]
UIM_DATA: C156.2 D16.C J8.10 SIM2.C7(I/O)  [project net UIM_DATA_7]
UIM_PWR: C152.2 C153.2 D13.C J8.8 SIM2.C1(VCC)  [project net UIM_PWR_7]
UIM_RST: C154.2 D14.C J8.14 SIM2.C2(RST)  [project net UIM_RST_7]
USB_DN: J8.36 ; port USB.D_N  [project net USB_H3.D_N]
USB_DP: J8.38 ; port USB.D_P  [project net USB_H3.D_P]
W_DISABLE: J8.20 ; port W_DISABLE  [project net A1]
NetJ8_7: J8.7 PCIE_CLKREQ.X R63.2

Not connected (* = marked no-connect by the designer): J8 1* 3* 5* 6* 16* 17* 19* 28* 42* 44* 45* 46* 47* 48* 49* 51* MP1(53)* MP2(54)*; SIM2 C6(VPP)*

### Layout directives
differential pair; differential pair class USB: USB_DN, USB_DP
differential pair; differential pair class PCIE: mPCIe_CK_N, mPCIe_CK_P, mPCIe_RX_N, mPCIe_RX_P, mPCIe_TX_N, mPCIe_TX_P

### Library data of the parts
C130-C133 = C0098-A.5: CAP CHIP 0603 47UF X5R 20%; Manufacturer: Murata; Voltage Rating: 6.3V; Code Arduino: C0098
C152 = C0012-A.9: as C25-C27 on sheet AUDIO
C153-C156 = C0097-A.6: CAP CHIP 0402 47PF 25V C0G 5%; Manufacturer: Yageo; Code Arduino: C0097
D13-D16 = D0027-A.4: DIODE TVS SMD 0402 14V 40V; Manufacturer: Littelfuse Inc; Device Type: ESD protection; Direction: Bidirectional; Code Arduino: 2280
H1-H4 = S0014-A.1: RND STANDOFF 7MM M2.5X0.45 STEEL; Manufacturer: Wurth Elektronik; Code Arduino: S0014
J8 = J0186-A.4: CONN PCI EXP MINI FEMALE 52POS Center board heigth 7.95mm; Manufacturer: TE Connectivity; Number of Positions: 52; PCB Mounting Orientation: Vertical; Code Arduino: J0186; Stack Height: 9.95mm; High Temperature Housing: Yes; PCB Mount Retention: Without; Stackable: No; Pitch: 0.8mm; Connector Type: Receptacle; Row Spacing: 0.031inch
PCIE_CLKREQ = UT0013-A.2: Test point 1.00mm
R63 = R0000-A.5: RES CHIP 0402 0R 1/16W; Manufacturer: Vishay; Code Arduino: 0039; Tolerance: J; Power: 63mW
SIM2 = J0149-A.2: CONN SIM NANO HINGED, 6P, 1.40MM PROF; Manufacturer: GCT; Code Arduino: J0149

## Sheet SD_CONNECTOR.SchDoc: SD CARD
size A4; Author: Arturo Guadalupi; CompanyName: Arduino srl; DocumentNumber: ABX00043; Revision: V3.10; SheetNumber: 10; SheetTotal: 14; RevAuthor: S. Navaretti
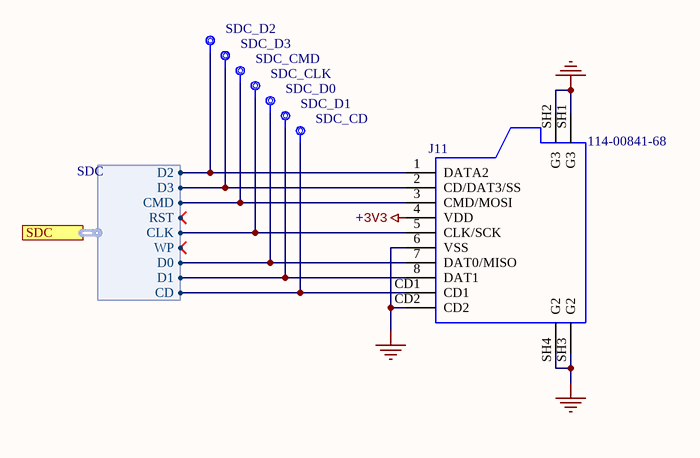
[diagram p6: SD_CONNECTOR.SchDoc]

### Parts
J11  114-00841-68  [AMPHENOL_114-00841-68]
SDC_CD  CMP-018-0005-A.3  [TP-1.00MM]  (value not drawn)  (no BOM)
SDC_CLK  CMP-018-0005-A.3  [TP-1.00MM]  (value not drawn)  (no BOM)
SDC_CMD  CMP-018-0005-A.3  [TP-1.00MM]  (value not drawn)  (no BOM)
SDC_D0  CMP-018-0005-A.3  [TP-1.00MM]  (value not drawn)  (no BOM)
SDC_D1  CMP-018-0005-A.3  [TP-1.00MM]  (value not drawn)  (no BOM)
SDC_D2  CMP-018-0005-A.3  [TP-1.00MM]  (value not drawn)  (no BOM)
SDC_D3  CMP-018-0005-A.3  [TP-1.00MM]  (value not drawn)  (no BOM)

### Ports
SDC (harness SDC)

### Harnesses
SDC: D0, D1, D2, D3, CMD, CLK, CD, WP, RST

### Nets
+3V3: J11.4(VDD)
GND: J11.6(VSS) J11.CD2 J11.SH1(G3) J11.SH2(G3) J11.SH3(G2) J11.SH4(G2)
SDC.CD: J11.CD1 SDC_CD.X ; port SDC.CD
SDC.CLK: J11.5(CLK/SCK) SDC_CLK.X ; port SDC.CLK
SDC.CMD: J11.3(CMD/MOSI) SDC_CMD.X ; port SDC.CMD
SDC.D0: J11.7(DAT0/MISO) SDC_D0.X ; port SDC.D0
SDC.D1: J11.8(DAT1) SDC_D1.X ; port SDC.D1
SDC.D2: J11.1(DATA2) SDC_D2.X ; port SDC.D2
SDC.D3: J11.2(CD/DAT3/SS) SDC_D3.X ; port SDC.D3

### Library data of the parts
J11 = J0011-A.4: CONN Micro SD; Manufacturer: Amphenol; Code Arduino: A5328
SDC_CD SDC_CLK SDC_CMD SDC_D0-SDC_D3 = UT0013-A.2: Test point 1.00mm

## Sheet CELL_MODEM.SchDoc: CELL MODEM
size A3; Author: Arturo Guadalupi; CompanyName: Arduino srl; DocumentNumber: ABX00043; Revision: V3.10; SheetNumber: 5; SheetTotal: 14; RevAuthor: S. Navaretti
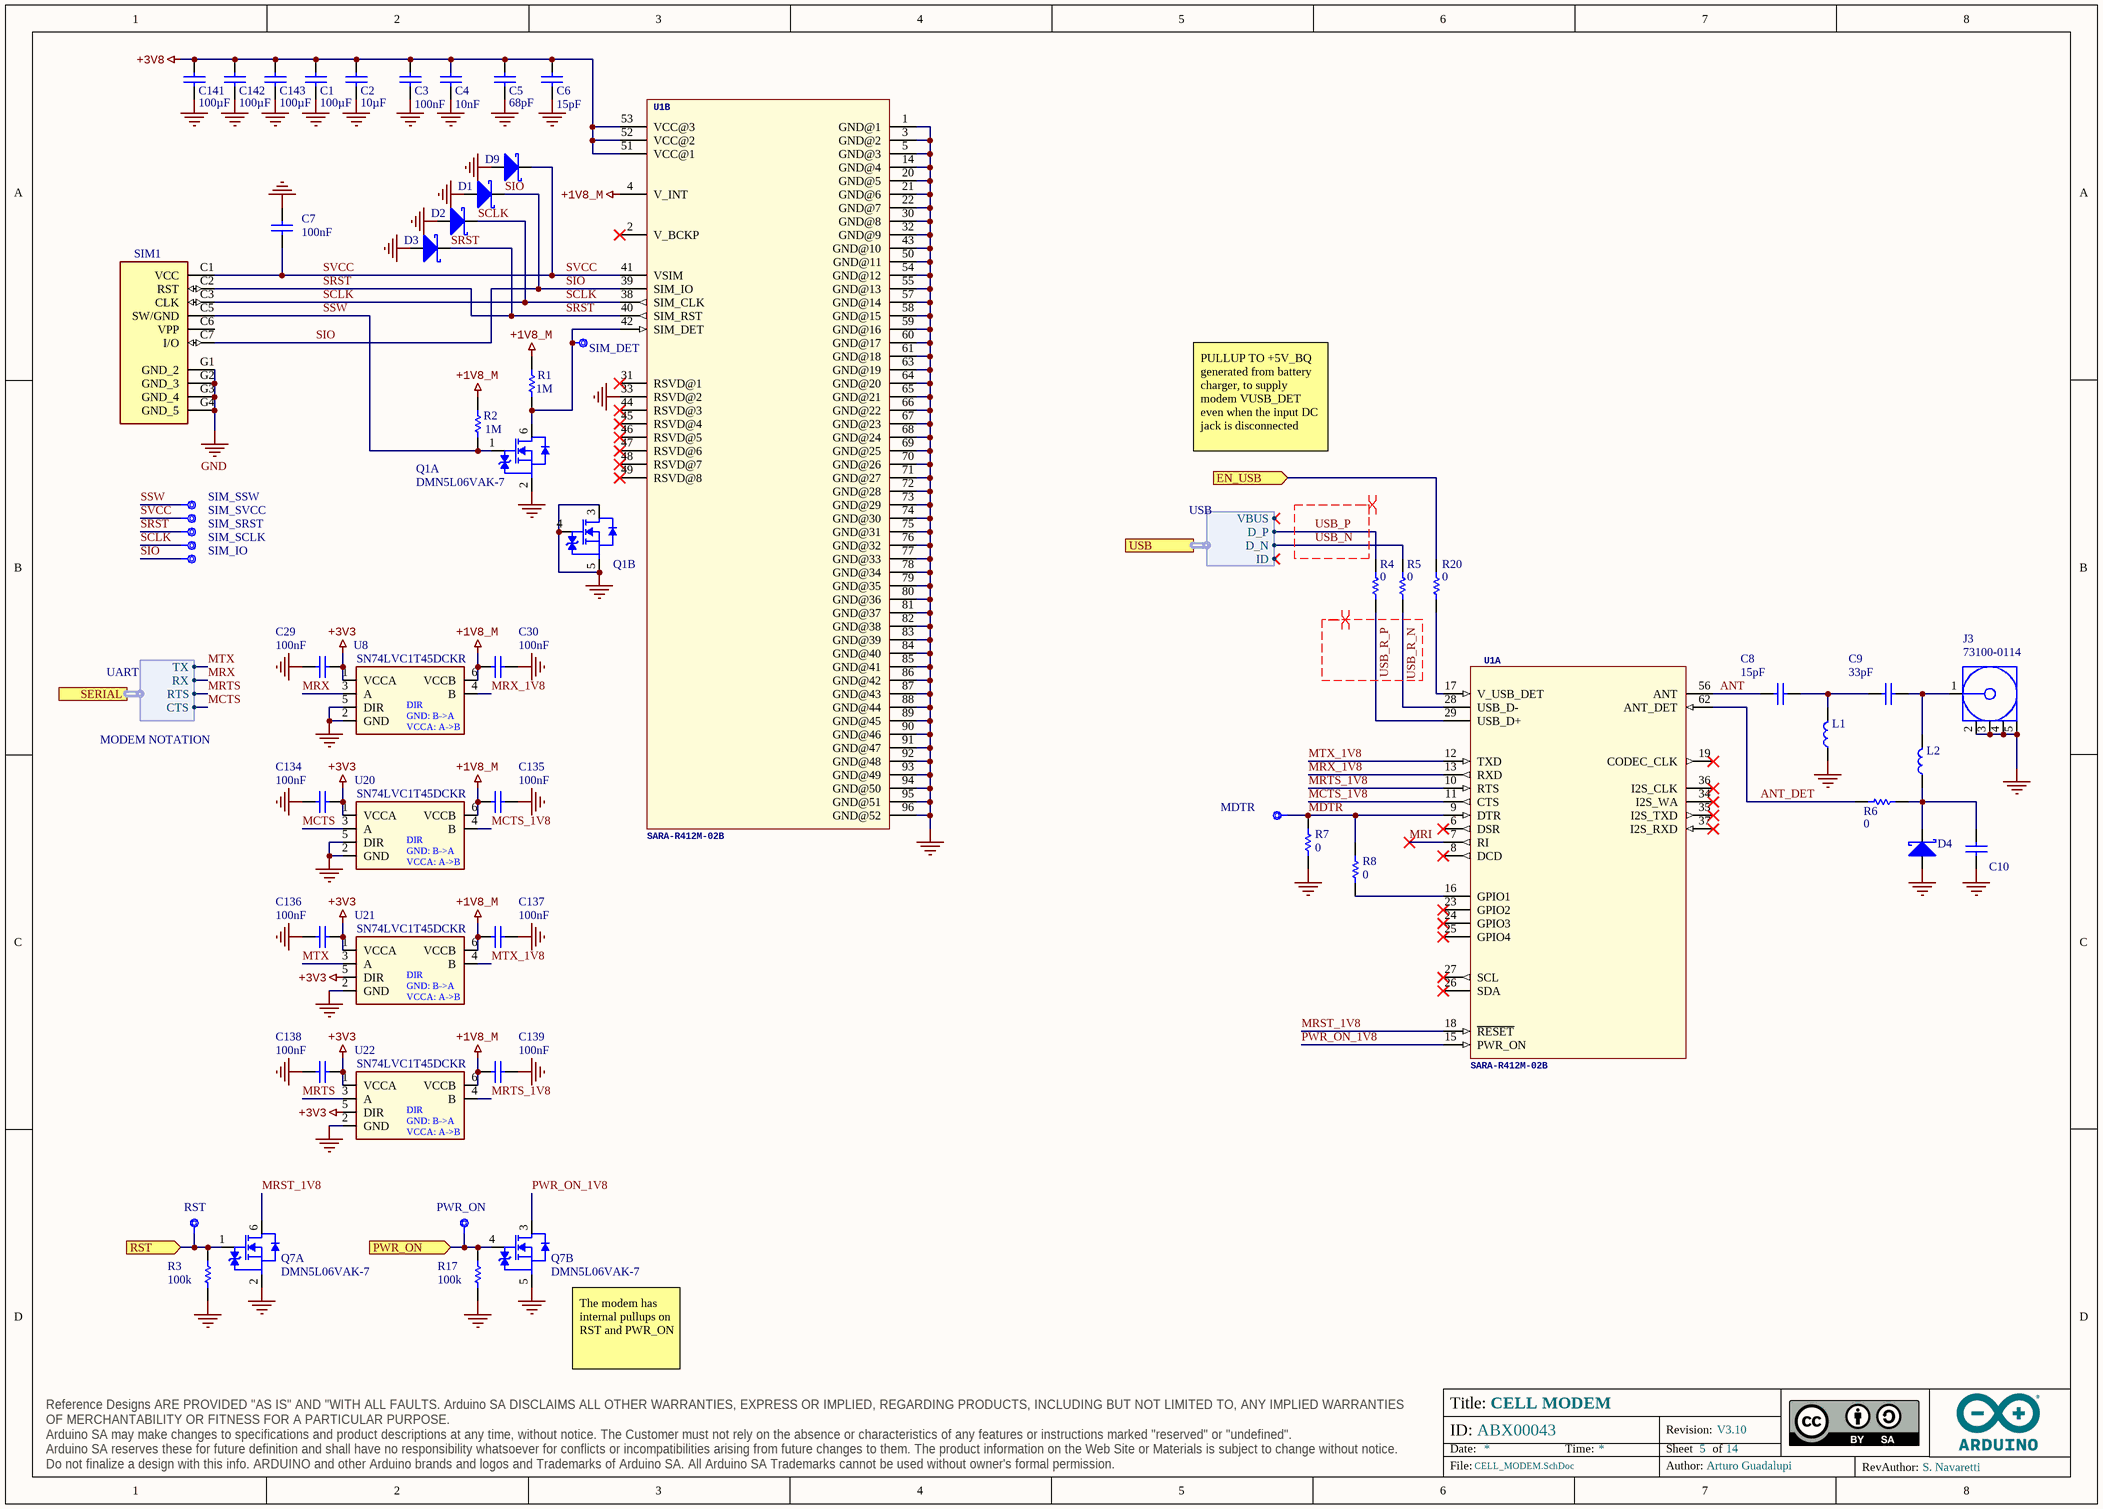
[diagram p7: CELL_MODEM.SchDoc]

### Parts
C1  value 100µF  [CAP-1206]  (hidden comment: CL31A107MPHNNNE)
C2  value 10µF  [CAP-0603]  (hidden comment: GRM188R61E106MA73J)
C3  value 100nF  [CAP-0402]  (hidden comment: C0402C104K4RACTU)
C4  value 10nF  [CAP-0402]  (hidden comment: C0402C103K5RACTU)
C5  value 68pF  [CAP-0402]  (hidden comment: 04025A680JAT2A)
C6  value 15pF  [CAP-0402]  (hidden comment: C0402C150J5GACTU)
C7  value 100nF  [CAP-0402]  (hidden comment: C0402C104K4RACTU)
C8  value 15pF  [CAP-0402]  (hidden comment: C0402C150J5GACTU)
C9  value 33pF  [CAP-0402]  (hidden comment: GRM1555C1H330JA01D)
C10  C0402C104K4RACTU  [CAP-0402]  (value not drawn)
C29  value 100nF  [CAP-0402]  (hidden comment: C0402C104K4RACTU)
C30  value 100nF  [CAP-0402]  (hidden comment: C0402C104K4RACTU)
C134  value 100nF  [CAP-0402]  (hidden comment: C0402C104K4RACTU)
C135  value 100nF  [CAP-0402]  (hidden comment: C0402C104K4RACTU)
C136  value 100nF  [CAP-0402]  (hidden comment: C0402C104K4RACTU)
C137  value 100nF  [CAP-0402]  (hidden comment: C0402C104K4RACTU)
C138  value 100nF  [CAP-0402]  (hidden comment: C0402C104K4RACTU)
C139  value 100nF  [CAP-0402]  (hidden comment: C0402C104K4RACTU)
C141  value 100µF  [CAP-1206]  (hidden comment: CL31A107MPHNNNE)
C142  value 100µF  [CAP-1206]  (hidden comment: CL31A107MPHNNNE)
C143  value 100µF  [CAP-1206]  (hidden comment: CL31A107MPHNNNE)
D1  PESD0402-140CT-ND  [0402]  (value not drawn)
D2  PESD0402-140CT-ND  [0402]  (value not drawn)
D3  PESD0402-140CT-ND  [0402]  (value not drawn)
D4  PESD0402-140CT-ND  [0402]  (value not drawn)
D9  PESD0402-140CT-ND  [0402]  (value not drawn)
J3  73100-0114  [MOLX-731000114_V]
L1  LQG15HN39NJ02D  [0402]  (value not drawn)
L2  LQG15HS68NJ02D  [0402]  (value not drawn)
MDTR  CMP-018-0005-A.3  [TP-1.00MM]  (value not drawn)  (no BOM)
PWR_ON  CMP-018-0005-A.3  [TP-1.00MM]  (value not drawn)  (no BOM)
Q1  DMN5L06VAK-7  [SOTFL50P158X60-6N]  (parts A,B of 2)
Q7  DMN5L06VAK-7  [SOTFL50P158X60-6N]  (parts A,B of 2)
R1  value 1M  [RES-0402]  (hidden comment: CRCW04021M00FKED)
R2  value 1M  [RES-0402]  (hidden comment: CRCW04021M00FKED)
R3  value 100k  [RES-0402]  (hidden comment: CRCW0402100KFKEDC)
R4  value 0  [RES-0402]  (hidden comment: CRCW04020000Z0EDC)
R5  value 0  [RES-0402]  (hidden comment: CRCW04020000Z0EDC)
R6  value 0  [RES-0402]  (hidden comment: CRCW04020000Z0EDC)
R7  value 0  [RES-0402]  (hidden comment: CRCW04020000Z0EDC)
R8  value 0  [RES-0402]  (hidden comment: CRCW04020000Z0EDC)
R17  value 100k  [RES-0402]  (hidden comment: CRCW0402100KFKEDC)
R20  value 0  [RES-0402]  (hidden comment: CRCW04020000Z0EDC)
RST  CMP-018-0005-A.3  [TP-1.00MM]  (value not drawn)  (no BOM)
SIM1  SIM8060-6-0-14-00-A  [SIM8060-6-0-14-00-A-Footprint-1]  (value not drawn)
SIM_DET  CMP-018-0005-A.3  [TP-1.00MM]  (value not drawn)  (no BOM)
SIM_IO  CMP-018-0005-A.3  [TP-1.00MM]  (value not drawn)  (no BOM)
SIM_SCLK  CMP-018-0005-A.3  [TP-1.00MM]  (value not drawn)  (no BOM)
SIM_SRST  CMP-018-0005-A.3  [TP-1.00MM]  (value not drawn)  (no BOM)
SIM_SSW  CMP-018-0005-A.3  [TP-1.00MM]  (value not drawn)  (no BOM)
SIM_SVCC  CMP-018-0005-A.3  [TP-1.00MM]  (value not drawn)  (no BOM)
U1  SARA-R412M-02B  [SARA-96]  (parts A,B of 2)
U8  SN74LVC1T45DCKR  [sc70-6]
U20  SN74LVC1T45DCKR  [sc70-6]
U21  SN74LVC1T45DCKR  [sc70-6]
U22  SN74LVC1T45DCKR  [sc70-6]

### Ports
EN_USB (in), PWR_ON (in), RST (in), SERIAL (harness UART), USB (harness USB)

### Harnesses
USB: VBUS, D_N, D_P, ID
UART: RX, TX, RTS, CTS

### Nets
+1V8_M: C30.2 C135.2 C137.2 C139.2 R1.2 R2.2 U1.4(V_INT) U8.6(VCCB) U20.6(VCCB) U21.6(VCCB) U22.6(VCCB)
+3V3: C29.2 C134.2 C136.2 C138.2 U8.1(VCCA) U20.1(VCCA) U21.1(VCCA) U21.5(DIR) U22.1(VCCA) U22.5(DIR)
+3V8: C1.2 C2.2 C3.2 C4.2 C5.2 C6.2 C141.2 C142.2 C143.2 U1.51(VCC@1) U1.52(VCC@2) U1.53(VCC@3)
GND: C1.1 C2.1 C3.1 C4.1 C5.1 C6.1 C7.2 C10.1 C29.1 C30.1 C134.1 C135.1 C136.1 C137.1 C138.1 C139.1 C141.1 C142.1 C143.1 D1.A D2.A D3.A D4.A D9.A J3.2 J3.3 J3.4 J3.5 L1.1 Q1.2(SOURCEA) Q1.3(DRAINB) Q1.4(GATEB) Q1.5(SOURCEB) Q7.2(SOURCEA) Q7.5(SOURCEB) R3.1 R7.1 R17.1 SIM1.G1(GND_2) SIM1.G2(GND_3) SIM1.G3(GND_4) SIM1.G4(GND_5) U1.1(GND@1) U1.3(GND@2) U1.5(GND@3) U1.14(GND@4) U1.20(GND@5) U1.21(GND@6) U1.22(GND@7) U1.30(GND@8) U1.32(GND@9) U1.33(RSVD@2) U1.43(GND@10) U1.50(GND@11) U1.54(GND@12) U1.55(GND@13) U1.57(GND@14) U1.58(GND@15) U1.59(GND@16) U1.60(GND@17) U1.61(GND@18) U1.63(GND@19) U1.64(GND@20) U1.65(GND@21) U1.66(GND@22) U1.67(GND@23) U1.68(GND@24) U1.69(GND@25) U1.70(GND@26) U1.71(GND@27) U1.72(GND@28) U1.73(GND@29) U1.74(GND@30) U1.75(GND@31) U1.76(GND@32) U1.77(GND@33) U1.78(GND@34) U1.79(GND@35) U1.80(GND@36) U1.81(GND@37) U1.82(GND@38) U1.83(GND@39) U1.84(GND@40) U1.85(GND@41) U1.86(GND@42) U1.87(GND@43) U1.88(GND@44) U1.89(GND@45) U1.90(GND@46) U1.91(GND@47) U1.92(GND@48) U1.93(GND@49) U1.94(GND@50) U1.95(GND@51) U1.96(GND@52) U8.2(GND) U8.5(DIR) U20.2(GND) U20.5(DIR) U21.2(GND) U22.2(GND)
ANT: C8.1 U1.56(ANT)  [project net ANT_5]
ANT_DET: R6.1 U1.62(ANT_DET)  [project net ANT_DET_5]
CELL_PON: PWR_ON.X Q7.4(GATEB) R17.2 ; port PWR_ON
CELL_RST: Q7.1(GATEA) R3.2 RST.X ; port RST
MCTS: U20.3(A) ; port SERIAL.CTS  [project net SERIAL1.CTS]
MCTS_1V8: U1.11(CTS) U20.4(B)  [project net MCTS_1V8_5]
MDTR: MDTR.X R7.2 R8.2 U1.9(DTR)  [project net MDTR_5]
MRI: U1.7(RI)  [project net MRI_5]
MRST_1V8: Q7.6(DRAINA) U1.18(~{RESET})  [project net MRST_1V8_5]
MRTS: U22.3(A) ; port SERIAL.RTS  [project net SERIAL1.RTS]
MRTS_1V8: U1.10(RTS) U22.4(B)  [project net MRTS_1V8_5]
MRX: U8.3(A) ; port SERIAL.RX  [project net SERIAL1.RX]
MRX_1V8: U1.13(RXD) U8.4(B)  [project net MRX_1V8_5]
MTX: U21.3(A) ; port SERIAL.TX  [project net SERIAL1.TX]
MTX_1V8: U1.12(TXD) U21.4(B)  [project net MTX_1V8_5]
PWR_ON_1V8: Q7.3(DRAINB) U1.15(PWR_ON)  [project net PWR_ON_1V8_5]
SCLK: D2.C SIM1.C3(CLK) SIM_SCLK.X U1.38(SIM_CLK)  [project net SCLK_5]
SIO: D1.C SIM1.C7(I/O) SIM_IO.X U1.39(SIM_IO)  [project net SIO_5]
SRST: D3.C SIM1.C2(RST) SIM_SRST.X U1.40(SIM_RST)  [project net SRST_5]
SSW: Q1.1(GATEA) R2.1 SIM1.C5(SW/GND) SIM_SSW.X  [project net SSW_5]
SVCC: C7.1 D9.C SIM1.C1(VCC) SIM_SVCC.X U1.41(VSIM)  [project net SVCC_5]
USB_EN2: R20.2 ; port EN_USB
USB_N: R5.2 ; port USB.D_N  [project net USB_H2.D_N]
USB_P: R4.2 ; port USB.D_P  [project net USB_H2.D_P]
USB_R_N: R5.1 U1.28(USB_D-)  [project net USB_R_N_5]
USB_R_P: R4.1 U1.29(USB_D+)  [project net USB_R_P_5]
NetC8_2: C8.2 C9.1 L1.2
NetC9_2: C9.2 J3.1 L2.2
NetC10_2: C10.2 D4.C L2.1 R6.2
NetQ1_6: Q1.6(DRAINA) R1.1 SIM_DET.X U1.42(SIM_DET)
NetR8_1: R8.1 U1.16(GPIO1)
NetR20_1: R20.1 U1.17(V_USB_DET)

Not connected (* = marked no-connect by the designer): SIM1 C6(VPP); U1 2(V_BCKP)* 6(DSR)* 8(DCD)* 19(CODEC_CLK)* 23(GPIO2)* 24(GPIO3)* 25(GPIO4)* 26(SDA)* 27(SCL)* 31(RSVD@1)* 34(I2S_WA)* 35(I2S_TXD)* 36(I2S_CLK)* 37(I2S_RXD)* 44(RSVD@3)* 45(RSVD@4)* 46(RSVD@5)* 47(RSVD@6)* 48(RSVD@7)* 49(RSVD@8)*

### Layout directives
differential pair; differential pair class USB: USB_N, USB_P, USB_R_N, USB_R_P

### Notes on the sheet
- PULLUP TO +5V_BQ generated from battery charger, to supply modem VUSB_DET even when the input DC jack is disconnected
- MODEM NOTATION
- (near Q7) The modem has internal pullups on RST and PWR_ON

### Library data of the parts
C1 C141-C143 = C0062-A.9: CAP CHIP 1206 100UF 10V X5R 20%; Manufacturer: Samsung; Code Arduino: A5503
C2 = C0047-A.12: CAP CHIP 0603 10uF 25V X5R 20%; Manufacturer: Murata; Part Number: C1608X5R1A226MT000N; Code Arduino: 2213
C3 C7 C10 C29 C30 C134-C139 = C0012-A.9: as C25-C27 on sheet AUDIO
C4 = C0009-A.9: CAP CHIP 0402 10nF 50V X7R 10%; Manufacturer: KEMET; Code Arduino: 0165
C5 = C0032-A.7: CAP CHIP 0402 68pF C0G 50V 5%; Manufacturer: AVX; Code Arduino: A5496
C6 C8 = C0025-A.9: CAP CHIP 0402 15PF 50V C0G 5%; Manufacturer: Murata; Code Arduino: A5498
C9 = C0034-A.9: CAP CHIP 0402 33PF 50V C0G 5%; Manufacturer: Murata; Code Arduino: A5494
D1-D4 D9 = D0027-A.3: DIODE TVS SMD 0402 14V 40V; Manufacturer: Littelfuse Inc; Code Arduino: 2280; Device Type: ESD protection
J3 = J0084-A.2: CONN PCB JACK RECEPTACLE SMA RA 50 OHM; Manufacturer: Molex; Impedance: 50R; Dielectric Material: PTFE; Body Plating: Gold; Connector Type: SMA,Socket; Frequency: 12Hz; Max Frequency: 18GHz; Code Arduino: J0084; Body Material: Brass; Voltage Rating: 500V
L1 = I0023-A.4: IND CHIP 0402 39NH; Manufacturer: Murata; Code Arduino: A5497; Current: 250mA
L2 = I0020-A.4: IND CHIP 0402 68NH 250MA 5%; Manufacturer: Murata; Code Arduino: A5499
MDTR PWR_ON RST SIM_DET SIM_IO SIM_SCLK SIM_SRST SIM_SSW SIM_SVCC = UT0013-A.2: Test point 1.00mm
Q1 Q7 = T0023-A.5: MOSFET 2N-CH 50V 0.28A SOT-563; Manufacturer: Diodes Incorporated; Number of Elements: 2; Code Arduino: T0023; Element Configuration: Dual; FET Type: 2 N-Channel; Max Power Dissipation: 250mW; Gate to Source Voltage (Vgs): 20V; Continuous Drain Current (ID): 280mA; Rds On Max: 2R; Input Capacitance: 50pF
R1 R2 = R0058-A.5: RES CHIP 0402 1M 1% 1/16W; Manufacturer: Vishay; Code Arduino: 0139; Power: 63mW
R3 R17 = R0001-A.5: RES CHIP 0402 100K 1% 1/16W; Manufacturer: Vishay; Code Arduino: 0134; Power: 63mW
R4 R5 R20 = R0000-A.5: RES CHIP 0402 0R 1/16W; Manufacturer: Vishay; Tolerance: J; Code Arduino: 0039; Power: 63mW
R6-R8 = R0000-A.5: as R63 on sheet MINI_PCIE
SIM1 = J0149-A.2: as SIM2 on sheet MINI_PCIE
U1 = M0006-A.4: MODULE RF TXRX CELL 4G LTE CATM1/NB-IOT; Manufacturer: UBlox
U8 U20-U22 = U0019-A.7: IC TRANSLATOR BIDIR 1CH; Manufacturer: Texas Instruments; Device Type: BIDIR LEVEL SHIFTER; Code Arduino: A5331

## Sheet USB_HUB.SchDoc: USB HUB
size A4; Author: Arturo Guadalupi; CompanyName: Arduino srl; DocumentNumber: ABX00043; Revision: V3.10; SheetNumber: 8; SheetTotal: 14; RevAuthor: S. Navaretti
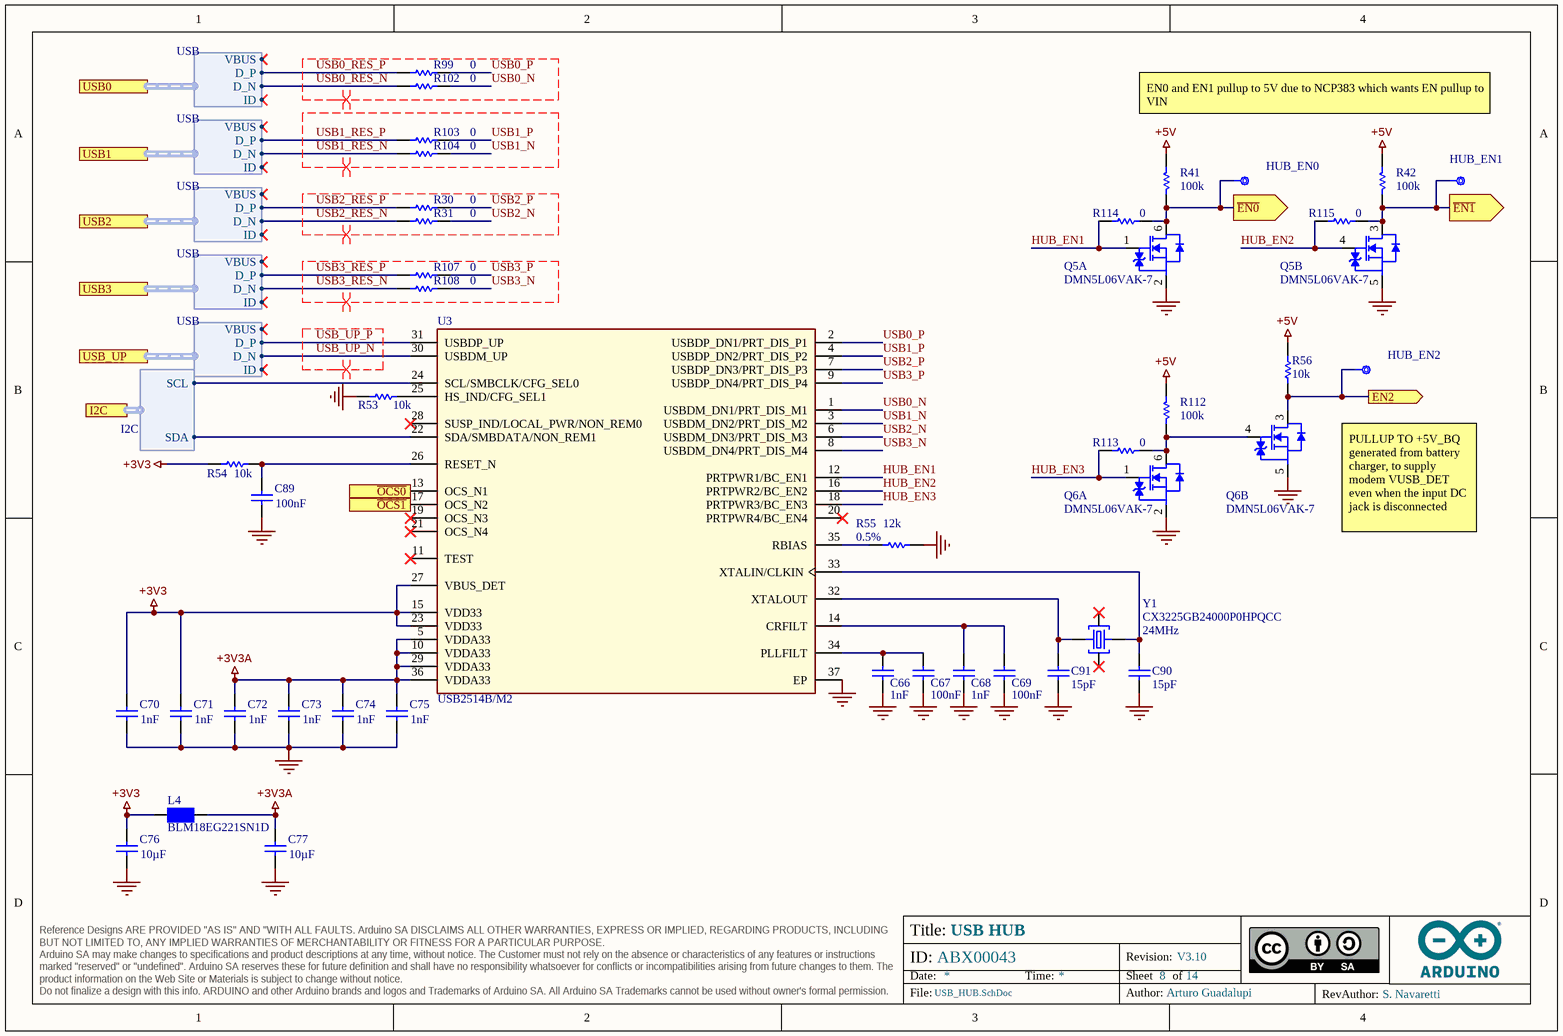
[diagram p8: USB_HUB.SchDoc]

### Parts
C66  value 1nF  [CAP-0402]  (hidden comment: C0402C100K5RACTU)
C67  value 100nF  [CAP-0402]  (hidden comment: C0402C104K4RACTU)
C68  value 1nF  [CAP-0402]  (hidden comment: C0402C100K5RACTU)
C69  value 100nF  [CAP-0402]  (hidden comment: C0402C104K4RACTU)
C70  value 1nF  [CAP-0402]  (hidden comment: C0402C100K5RACTU)
C71  value 1nF  [CAP-0402]  (hidden comment: C0402C100K5RACTU)
C72  value 1nF  [CAP-0402]  (hidden comment: C0402C100K5RACTU)
C73  value 1nF  [CAP-0402]  (hidden comment: C0402C100K5RACTU)
C74  value 1nF  [CAP-0402]  (hidden comment: C0402C100K5RACTU)
C75  value 1nF  [CAP-0402]  (hidden comment: C0402C100K5RACTU)
C76  value 10µF  [CAP-0603]  (hidden comment: GRM188R61E106MA73J)
C77  value 10µF  [CAP-0603]  (hidden comment: GRM188R61E106MA73J)
C89  value 100nF  [CAP-0402]  (hidden comment: C0402C104K4RACTU)
C90  value 15pF  [CAP-0402]  (hidden comment: C0402C150J5GACTU)
C91  value 15pF  [CAP-0402]  (hidden comment: C0402C150J5GACTU)
HUB_EN0  CMP-018-0005-A.3  [TP-1.00MM]  (value not drawn)  (no BOM)
HUB_EN1  CMP-018-0005-A.3  [TP-1.00MM]  (value not drawn)  (no BOM)
HUB_EN2  CMP-018-0005-A.3  [TP-1.00MM]  (value not drawn)  (no BOM)
L4  BLM18EG221SN1D  [L-0603]
Q5  DMN5L06VAK-7  [SOTFL50P158X60-6N]  (parts A,B of 2)
Q6  DMN5L06VAK-7  [SOTFL50P158X60-6N]  (parts A,B of 2)
R30  value 0  [RES-0402]  (hidden comment: CRCW04020000Z0EDC)
R31  value 0  [RES-0402]  (hidden comment: CRCW04020000Z0EDC)
R41  value 100k  [RES-0402]  (hidden comment: CRCW0402100KFKEDC)
R42  value 100k  [RES-0402]  (hidden comment: CRCW0402100KFKEDC)
R53  value 10k  [RES-0402]  (hidden comment: CRCW040210K0FKED)
R54  value 10k  [RES-0402]  (hidden comment: CRCW040210K0FKED)
R55  value 12k  Tolerance: 0.5%  [RES-0402]  (hidden comment: RR0510P-123-D)
R56  value 10k  [RES-0402]  (hidden comment: CRCW040210K0FKED)
R99  value 0  [RES-0402]  (hidden comment: CRCW04020000Z0EDC)
R102  value 0  [RES-0402]  (hidden comment: CRCW04020000Z0EDC)
R103  value 0  [RES-0402]  (hidden comment: CRCW04020000Z0EDC)
R104  value 0  [RES-0402]  (hidden comment: CRCW04020000Z0EDC)
R107  value 0  [RES-0402]  (hidden comment: CRCW04020000Z0EDC)
R108  value 0  [RES-0402]  (hidden comment: CRCW04020000Z0EDC)
R112  value 100k  [RES-0402]  (hidden comment: CRCW0402100KFKEDC)
R113  value 0  [RES-0402]  (hidden comment: CRCW04020000Z0EDC)
R114  value 0  [RES-0402]  (hidden comment: CRCW04020000Z0EDC)
R115  value 0  [RES-0402]  (hidden comment: CRCW04020000Z0EDC)
U3  USB2514B/M2  [MCHP-QFN-36_V]
Y1  CX3225GB24000P0HPQCC  Frequency: 24MHz  [CRYSTAL3.2X2.5]

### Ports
EN2 (out), I2C (harness I2C), USB0 (harness USB), USB1 (harness USB), USB2 (harness USB), USB3 (harness USB), USB_UP (harness USB), ~{EN0} (out), ~{EN1} (out), ~{OCS0} (in), ~{OCS1} (in)

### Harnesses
I2C: SCL, SDA
USB: VBUS, D_N, D_P, ID

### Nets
+3V3: C70.2 C71.2 C76.2 L4.1 R54.2 U3.15(VDD33) U3.23(VDD33) U3.27(VBUS_DET)
+3V3A: C72.2 C73.2 C74.2 C75.2 C77.2 L4.2 U3.5(VDDA33) U3.10(VDDA33) U3.29(VDDA33) U3.36(VDDA33)
+5V: R41.2 R42.2 R56.1 R112.2
GND: C66.1 C67.1 C68.1 C69.1 C70.1 C71.1 C72.1 C73.1 C74.1 C75.1 C76.1 C77.1 C89.1 C90.1 C91.1 Q5.2(SOURCEA) Q5.5(SOURCEB) Q6.2(SOURCEA) Q6.5(SOURCEB) R53.2 R55.2 U3.37(EP)
HUB_EN1: Q5.1(GATEA) R114.1 U3.12(PRTPWR1/BC_EN1)  [project net HUB_EN1_8]
HUB_EN2: Q5.4(GATEB) R115.1 U3.16(PRTPWR2/BC_EN2)  [project net HUB_EN2_8]
HUB_EN3: Q6.1(GATEA) R113.1 U3.18(PRTPWR3/BC_EN3)  [project net HUB_EN3_8]
I2C0.SCL: U3.24(SCL/SMBCLK/CFG_SEL0) ; port I2C.SCL
I2C0.SDA: U3.22(SDA/SMBDATA/NON_REM1) ; port I2C.SDA
~{USB_EN0}: HUB_EN0.X Q5.6(DRAINA) R41.1 R114.2 ; port ~{EN0}
~{USB_EN1}: HUB_EN1.X Q5.3(DRAINB) R42.1 R115.2 ; port ~{EN1}
USB0_N: R102.2 U3.1(USBDM_DN1/PRT_DIS_M1)  [project net USB0_N_8]
USB0_P: R99.2 U3.2(USBDP_DN1/PRT_DIS_P1)  [project net USB0_P_8]
USB0_RES_N: R102.1 ; port USB0.D_N  [project net USB_H0.D_N]
USB0_RES_P: R99.1 ; port USB0.D_P  [project net USB_H0.D_P]
USB1_N: R104.2 U3.3(USBDM_DN2/PRT_DIS_M2)  [project net USB1_N_8]
USB1_P: R103.2 U3.4(USBDP_DN2/PRT_DIS_P2)  [project net USB1_P_8]
USB1_RES_N: R104.1 ; port USB1.D_N  [project net USB_H1.D_N]
USB1_RES_P: R103.1 ; port USB1.D_P  [project net USB_H1.D_P]
USB2_N: R31.2 U3.6(USBDM_DN3/PRT_DIS_M3)  [project net USB2_N_8]
USB2_P: R30.2 U3.7(USBDP_DN3/PRT_DIS_P3)  [project net USB2_P_8]
USB2_RES_N: R31.1 ; port USB2.D_N  [project net USB_H2.D_N]
USB2_RES_P: R30.1 ; port USB2.D_P  [project net USB_H2.D_P]
USB3_N: R108.2 U3.8(USBDM_DN4/PRT_DIS_M4)  [project net USB3_N_8]
USB3_P: R107.2 U3.9(USBDP_DN4/PRT_DIS_P4)  [project net USB3_P_8]
USB3_RES_N: R108.1 ; port USB3.D_N  [project net USB_H3.D_N]
USB3_RES_P: R107.1 ; port USB3.D_P  [project net USB_H3.D_P]
USB_EN2: HUB_EN2.X Q6.3(DRAINB) R56.2 ; port EN2
USB_OC0: U3.13(OCS_N1) ; port ~{OCS0}
USB_OC1: U3.17(OCS_N2) ; port ~{OCS1}
USB_UP_N: U3.30(USBDM_UP) ; port USB_UP.D_N  [project net USB_FS.D_N]
USB_UP_P: U3.31(USBDP_UP) ; port USB_UP.D_P  [project net USB_FS.D_P]
NetC66_2: C66.2 C67.2 U3.34(PLLFILT)
NetC68_2: C68.2 C69.2 U3.14(CRFILT)
NetC89_2: C89.2 R54.1 U3.26(RESET_N)
NetC90_2: C90.2 U3.33(XTALIN/CLKIN) Y1.3
NetC91_2: C91.2 U3.32(XTALOUT) Y1.1
NetQ6_4: Q6.4(GATEB) Q6.6(DRAINA) R112.1 R113.2
NetR53_1: R53.1 U3.25(HS_IND/CFG_SEL1)
NetR55_1: R55.1 U3.35(RBIAS)

Not connected (* = marked no-connect by the designer): U3 11(TEST)* 19(OCS_N3)* 20(PRTPWR4/BC_EN4)* 21(OCS_N4)* 28(SUSP_IND/LOCAL_PWR/NON_REM0)*; Y1 2* 4*

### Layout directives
differential pair; differential pair class USB: USB0_N, USB0_P, USB0_RES_N, USB0_RES_P, USB1_N, USB1_P, USB1_RES_N, USB1_RES_P, USB2_N, USB2_P, USB2_RES_N, USB2_RES_P, USB3_N, USB3_P, USB3_RES_N, USB3_RES_P, USB_UP_N, USB_UP_P

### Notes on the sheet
- EN0 and EN1 pullup to 5V due to NCP383 which wants EN pullup to VIN
- PULLUP TO +5V_BQ generated from battery charger, to supply modem VUSB_DET even when the input DC jack is disconnected

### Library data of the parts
C66 C68 C70-C75 = C0007-A.9: CAP CHIP 0402 1nF 50V X7R 10%; Manufacturer: KEMET; Code Arduino: 2321
C67 C69 C89 = C0012-A.9: as C25-C27 on sheet AUDIO
C76 C77 = C0047-A.12: CAP CHIP 0603 10uF 25V X5R 20%; Part Number: C1608X5R1A226MT000N; Manufacturer: Murata; Code Arduino: 2213
C90 C91 = C0025-A.9: as C6 on sheet CELL_MODEM
HUB_EN0-HUB_EN2 = UT0013-A.2: Test point 1.00mm
L4 = I0021-A.3: FERRITE SMD 0603 220 OHM 2A; Manufacturer: Murata; Impedance: 220µH; Code Arduino: A5489; Test Frequency: 100MHz; Tolerance: 25%; DC Resistance (DCR): 50mR
Q5 Q6 = T0023-A.5: as Q1 on sheet CELL_MODEM
R30 R31 R99 R102-R104 R107 R108 = R0000-A.5: RES CHIP 0402 0R 1/16W; Manufacturer: Vishay; Tolerance: J; Power: 63mW; Code Arduino: 0039
R41 R42 R112 = R0001-A.5: as R24 on sheet AUDIO
R53 R54 R56 = R0003-A.5: RES CHIP 0402 10K 1% 1/16W; Manufacturer: Vishay; Code Arduino: 0136; Power: 63mW
R55 = R0167-A.4: RES CHIP 0402 12K 0.5% 1/16W; Manufacturer: Susumu; Code Arduino: R0167; Power: 63mW
R113-R115 = R0000-A.5: as R119 on sheet HDConn_FEMALE
U3 = U0115-A.4: IC USB 2.0 4PORT HUB CTLR 36QFN; Manufacturer: Microchip; Data Rate: 480Mbps; Operating Supply Voltage: 3.3V; Code Arduino: U0115; Max Supply Voltage: 3.6V; Min Supply Voltage: 3V; Operating Supply Current: 70mA
Y1 = X0005-A.4: CRYSTAL 24.0000MHZ 18PF SMD; Manufacturer: Kyocera; Frequency Tolerance: 20ppm; Code Arduino: X0005; ESR (Equivalent Series Resistance): 60; Series Resistance: 60R; Frequency Stability: 30ppm

## Sheet USBA_CONNECTORS.SchDoc: USB CONNECTORS
size A4; Author: Arturo Guadalupi; CompanyName: Arduino srl; DocumentNumber: ABX00043; Revision: V3.10; SheetNumber: 9; SheetTotal: 14; RevAuthor: S. Navaretti
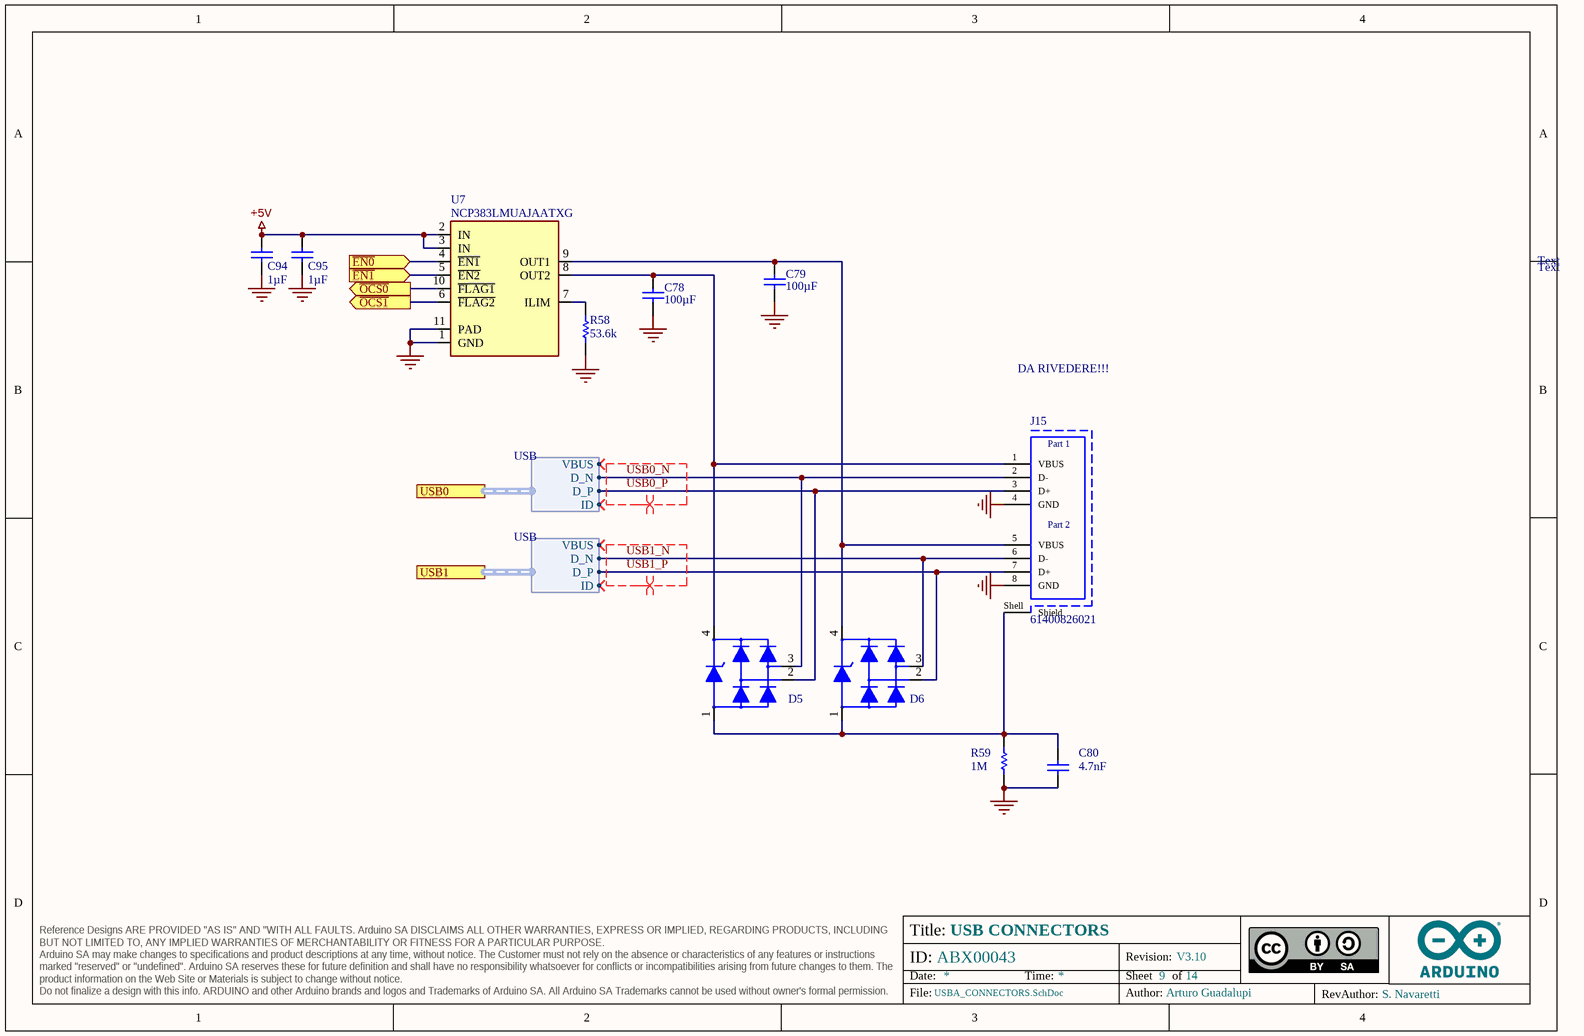
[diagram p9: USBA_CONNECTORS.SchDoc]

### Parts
C78  value 100µF  [CAP-1206]  (hidden comment: CL31A107MPHNNNE)
C79  value 100µF  [CAP-1206]  (hidden comment: CL31A107MPHNNNE)
C80  value 4.7nF  [CAP-0805]  (hidden comment: C0805C472KDRACTU)
C94  value 1µF  [CAP-0402]  (hidden comment: C0402C105K8PACTU)
C95  value 1µF  [CAP-0402]  (hidden comment: C0402C105K8PACTU)
D5  PRTR5V0U2X,215  [SOT190P230X110-4N]  (value not drawn)
D6  PRTR5V0U2X,215  [SOT190P230X110-4N]  (value not drawn)
J15  61400826021  [61400826021]
R58  value 53.6k  [RES-0402]  (hidden comment: CRCW040253K6FKED)
R59  value 1M  [RES-0402]  (hidden comment: CRCW04021M00FKED)
U7  NCP383LMUAJAATXG  [PQFN50P300X300X55_HS-21L]

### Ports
USB0 (harness USB), USB1 (harness USB), ~{EN0} (in), ~{EN1} (in), ~{OCS0} (out), ~{OCS}~{1} (out)

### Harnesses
USB: VBUS, D_N, D_P, ID

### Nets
+5V: C94.2 C95.2 U7.2(IN) U7.3(IN)
GND: C78.1 C79.1 C80.1 C94.1 C95.1 J15.4(GND) J15.8(GND) R58.2 R59.1 U7.1(GND) U7.11(PAD)
~{USB_EN0}: U7.4(~{EN1}) ; port ~{EN0}
~{USB_EN1}: U7.5(~{EN2}) ; port ~{EN1}
USB0_N: D5.3 J15.2(D-) ; port USB0.D_N  [project net USB_H0.D_N]
USB0_P: D5.2 J15.3(D+) ; port USB0.D_P  [project net USB_H0.D_P]
USB1_N: D6.3 J15.6(D-) ; port USB1.D_N  [project net USB_H1.D_N]
USB1_P: D6.2 J15.7(D+) ; port USB1.D_P  [project net USB_H1.D_P]
USB_OC0: U7.10(~{FLAG1}) ; port ~{OCS0}
USB_OC1: U7.6(~{FLAG2}) ; port ~{OCS}~{1}
NetC78_2: C78.2 D5.4 J15.1(VBUS) U7.8(OUT2)
NetC79_2: C79.2 D6.4 J15.5(VBUS) U7.9(OUT1)
NetC80_2: C80.2 D5.1 D6.1 J15.Shell(Shield) R59.2
NetR58_1: R58.1 U7.7(ILIM)

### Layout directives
differential pair; differential pair class USB: USB0_N, USB0_P, USB1_N, USB1_P

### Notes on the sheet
- Text
- DA RIVEDERE!!!

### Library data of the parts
C78 C79 = C0062-A.9: as C1 on sheet CELL_MODEM
C80 = C0059-A.9: CAP CHIP 0805 4.7nF 1000V X7R 10%; Manufacturer: KEMET; Voltage: 1kV; Code Arduino: 0689
C94 C95 = C0017-A.9: as C24 on sheet AUDIO
D5 D6 = D0025-A.3: TVS ARRAY 4LIN.8kV 1pF SOT143B; Manufacturer: Nexperia; Device Type: ESD protection; Code Arduino: 2209
J15 = J0087-A.2: CONN RCPT USB2.0 TYPEA STACK R/A; Manufacturer: Wurth Electronics; Connector Type: USB,Socket; Gender: Female; Number of Positions: 8; Voltage Rating: 30V; Code Arduino: J0087; Number of Ports: 2; Insulation Resistance: 1GR; Current Rating: 1A
R58 = R0050-A.5: RES CHIP 0402 53.6K 1% 1/16W; Manufacturer: Vishay; Power: 63mW; Code Arduino: A5313
R59 = R0058-A.5: RES CHIP 0402 1M 1% 1/16W; Manufacturer: Vishay; Power: 63mW; Code Arduino: 0139
U7 = U0052-A.5: IC POWER SWITCH DUAL CHANNEL OCP; Manufacturer: ON Semiconductor; Max Input Voltage: 5.5V; Min Input Voltage: 2.7V; Turn-Off Delay Time: 3ms; Number of Outputs: 2; Output Configuration: High Side; Turn-On Delay Time: 9ms; Interface: On/Off; Max Power Dissipation: 850mW; Code Arduino: U0052; On-State Resistance: 95mR; Max Output Current: 2.5A; Device Type: PWR SWITCH; Fault Protection: Over Temperature; Max Supply Current: 1uA

## Sheet CAMERA_CONNECTOR.SchDoc: CAMERA CONNECTOR
size A4; Author: Arturo Guadalupi; CompanyName: Arduino srl; DocumentNumber: ABX00043; Revision: V3.10; SheetNumber: 11; SheetTotal: 14; RevAuthor: S. Navaretti
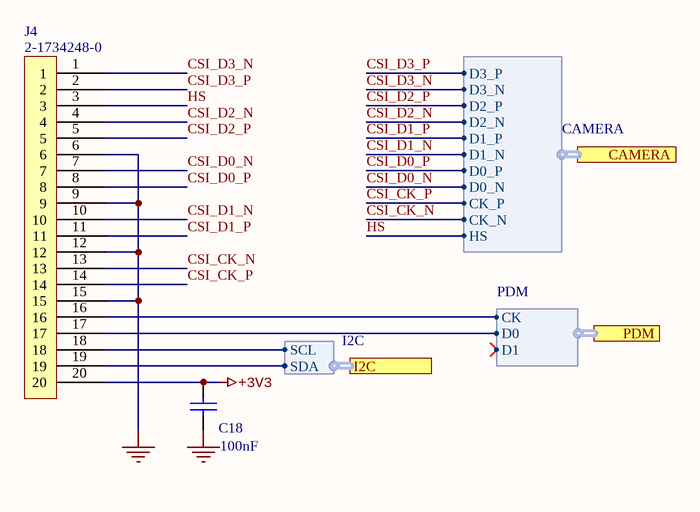
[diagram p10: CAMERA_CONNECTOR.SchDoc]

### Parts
C18  value 100nF  [CAP-0402]  (hidden comment: C0402C104K4RACTU)
J4  2-1734248-0  [2-1734248-0-Footprint-1]

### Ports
CAMERA (harness CAMERA), I2C (harness I2C), PDM (harness PDM)

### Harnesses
I2C: SCL, SDA
PDM: CK, D0, D1
CAMERA: D3_P, D3_N, D2_P, D2_N, D1_P, D1_N, D0_P, D0_N, CK_P, CK_N, HS

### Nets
+3V3: C18.2 J4.20
GND: C18.1 J4.6 J4.9 J4.12 J4.15
CSI_CK_N: J4.13 ; port CAMERA.CK_N  [project net CAMERA.CK_N]
CSI_CK_P: J4.14 ; port CAMERA.CK_P  [project net CAMERA.CK_P]
CSI_D0_N: J4.7 ; port CAMERA.D0_N  [project net CAMERA.D0_N]
CSI_D0_P: J4.8 ; port CAMERA.D0_P  [project net CAMERA.D0_P]
CSI_D1_N: J4.10 ; port CAMERA.D1_N  [project net CAMERA.D1_N]
CSI_D1_P: J4.11 ; port CAMERA.D1_P  [project net CAMERA.D1_P]
CSI_D2_N: J4.4 ; port CAMERA.D2_N  [project net CAMERA.D2_N]
CSI_D2_P: J4.5 ; port CAMERA.D2_P  [project net CAMERA.D2_P]
CSI_D3_N: J4.1 ; port CAMERA.D3_N  [project net CAMERA.D3_N]
CSI_D3_P: J4.2 ; port CAMERA.D3_P  [project net CAMERA.D3_P]
HS: J4.3 ; port CAMERA.HS  [project net CAMERA.HS]
I2C0.SCL: J4.18 ; port I2C.SCL
I2C0.SDA: J4.19 ; port I2C.SDA
PDM.CK: J4.16 ; port PDM.CK
PDM.D0: J4.17 ; port PDM.D0

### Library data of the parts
C18 = C0012-A.9: as C25-C27 on sheet AUDIO
J4 = J0081-A.3: CONN FPC VERT 20POS 1.00MM SMD; Manufacturer: TE Connectivity; Contact Location: Bottom; PCB Mounting Orientation: Vertical; Sealable: No (Without); Shielding: Unshielded; Wire/Cable Type: Flat Flex; Number of Contacts: 20; Code Arduino: J0081; PCB Mount Retention: With; Pitch: 0.039inch; Voltage Rating: 125V; Connector Type: Receptacle,Connector,Socket; Contact Current Rating: 1A; Shrouded: Yes (With); Gender: Male; Connector System: Flex-to-Board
